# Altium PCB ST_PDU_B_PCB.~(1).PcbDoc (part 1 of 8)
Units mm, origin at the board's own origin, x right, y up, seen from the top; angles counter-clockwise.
Board outline 200 x 200 mm, 6 copper layers (Top Layer, Layer 1, Layer 2, Layer 3, Layer 4, Bottom Layer), stack 3.194 mm thick; 894 components, 723 nets, 3233 pads, 4067 vias.
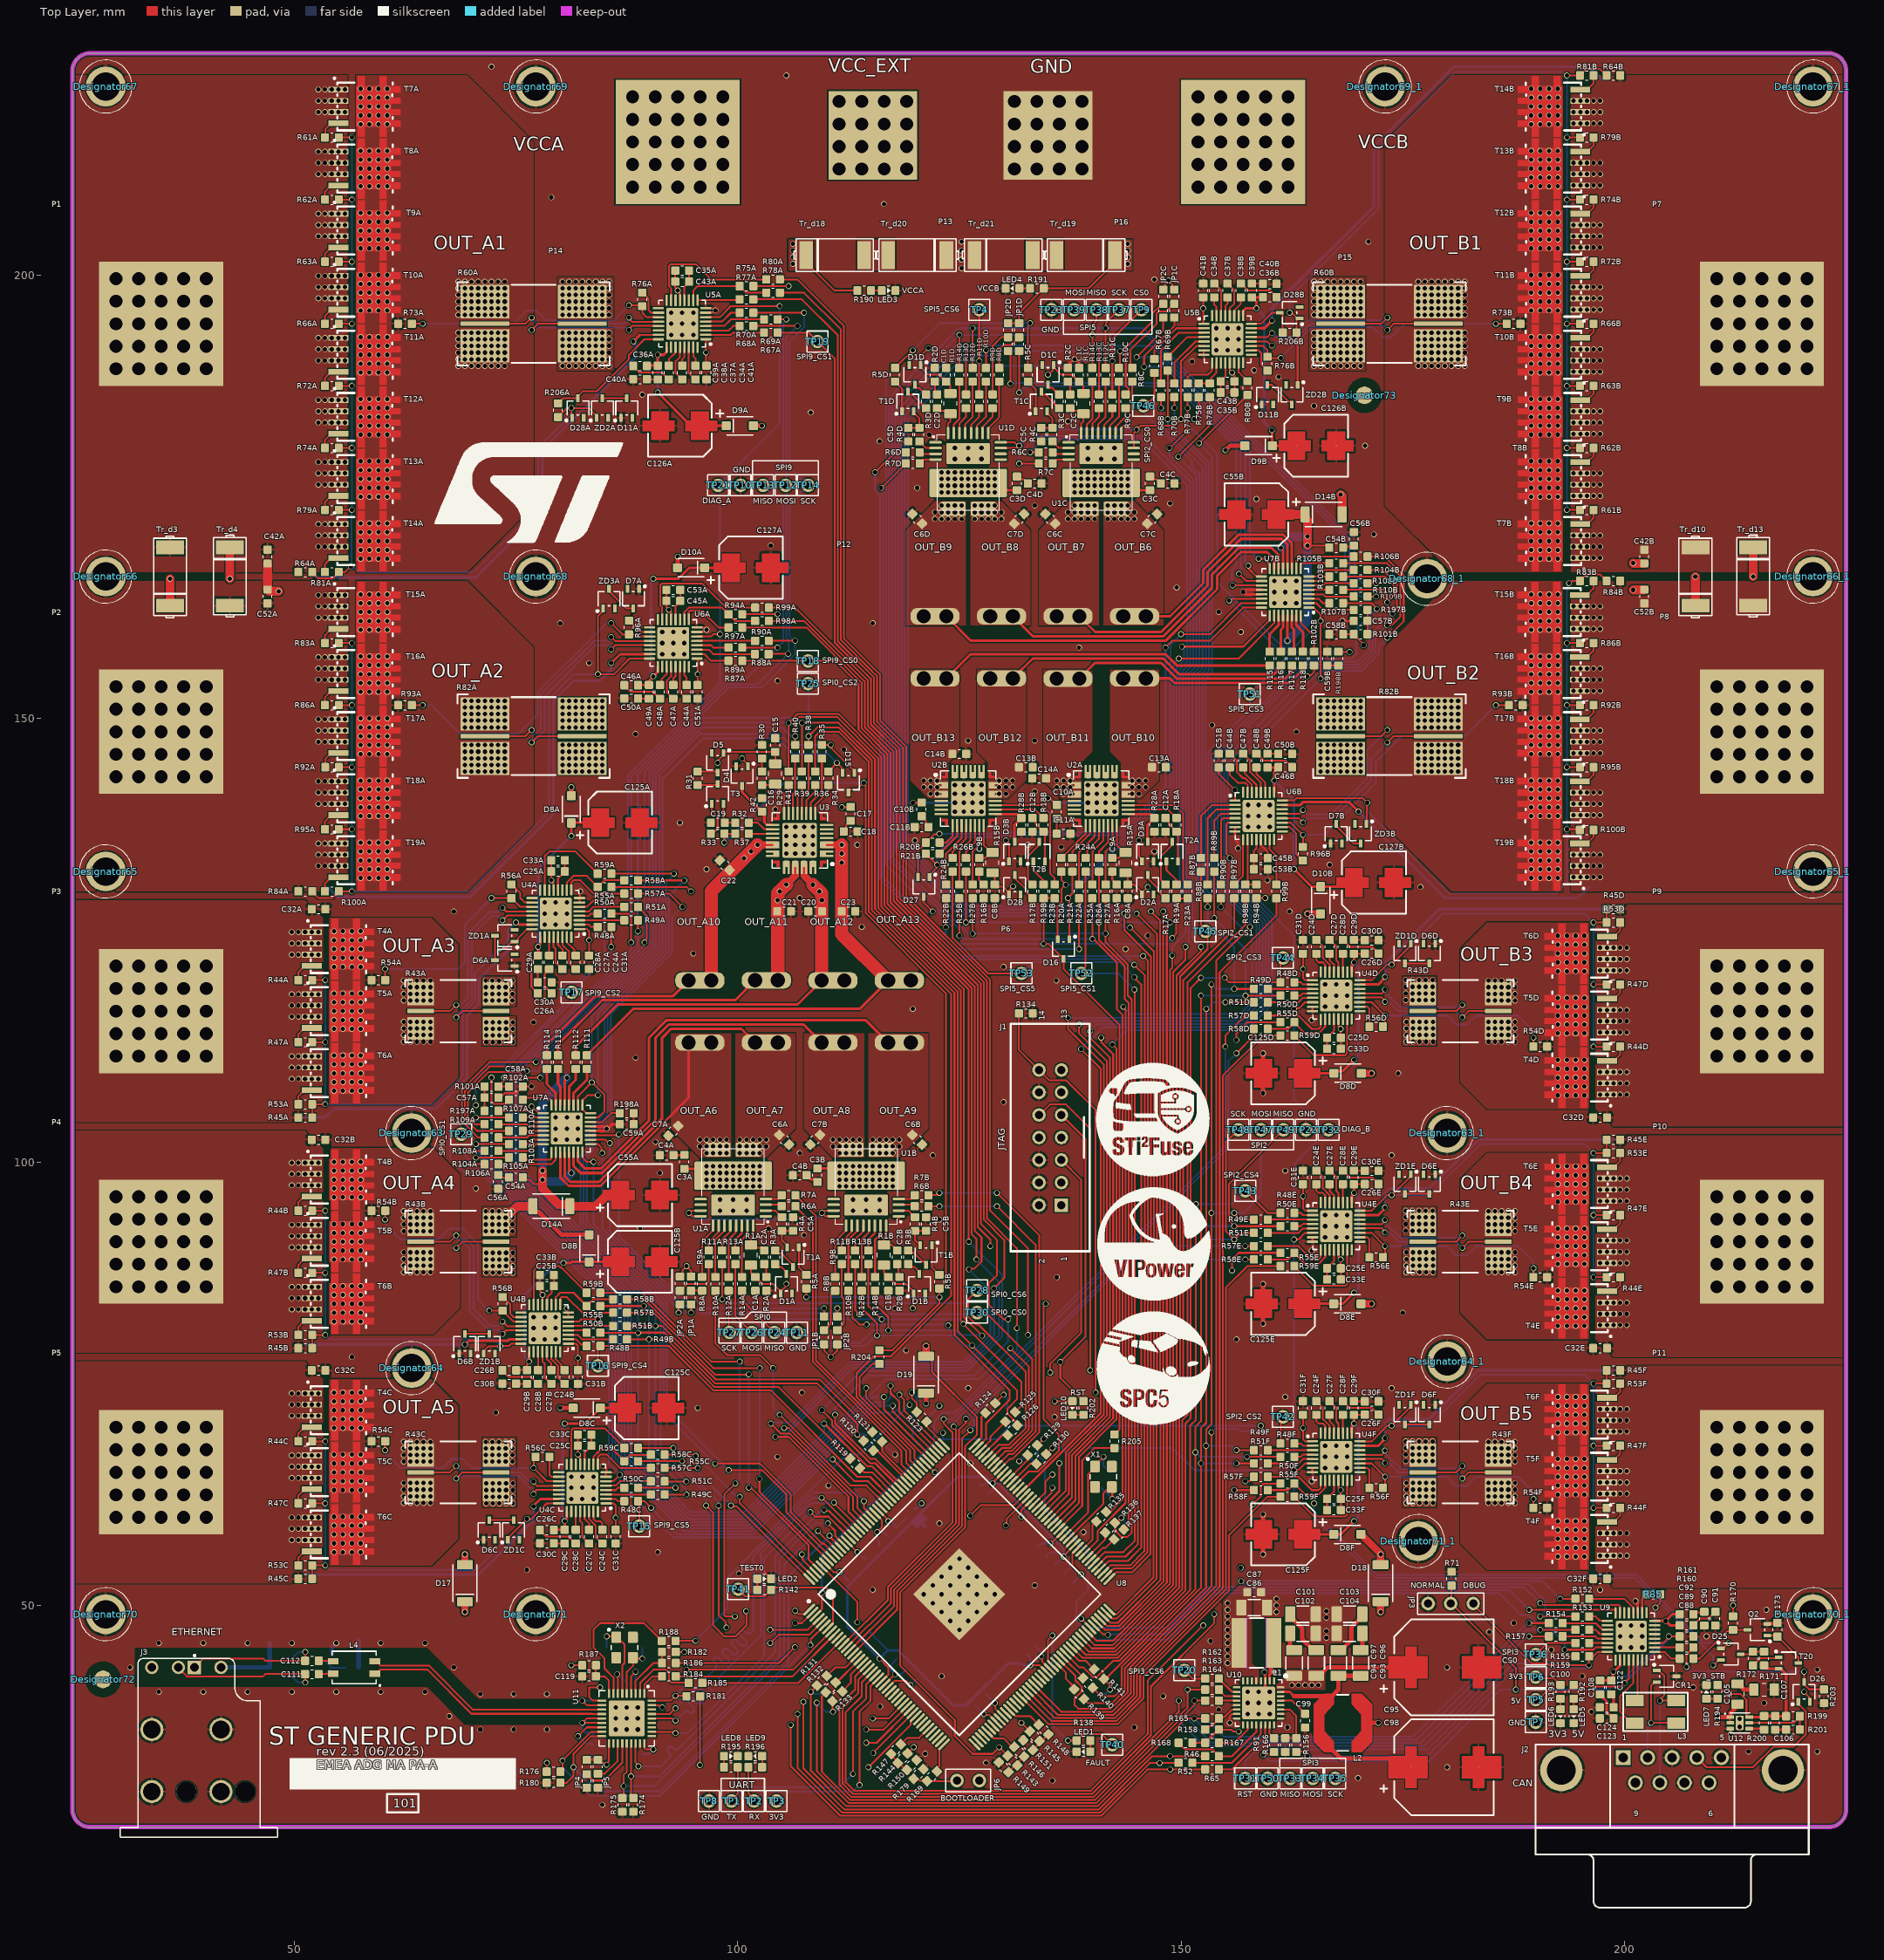
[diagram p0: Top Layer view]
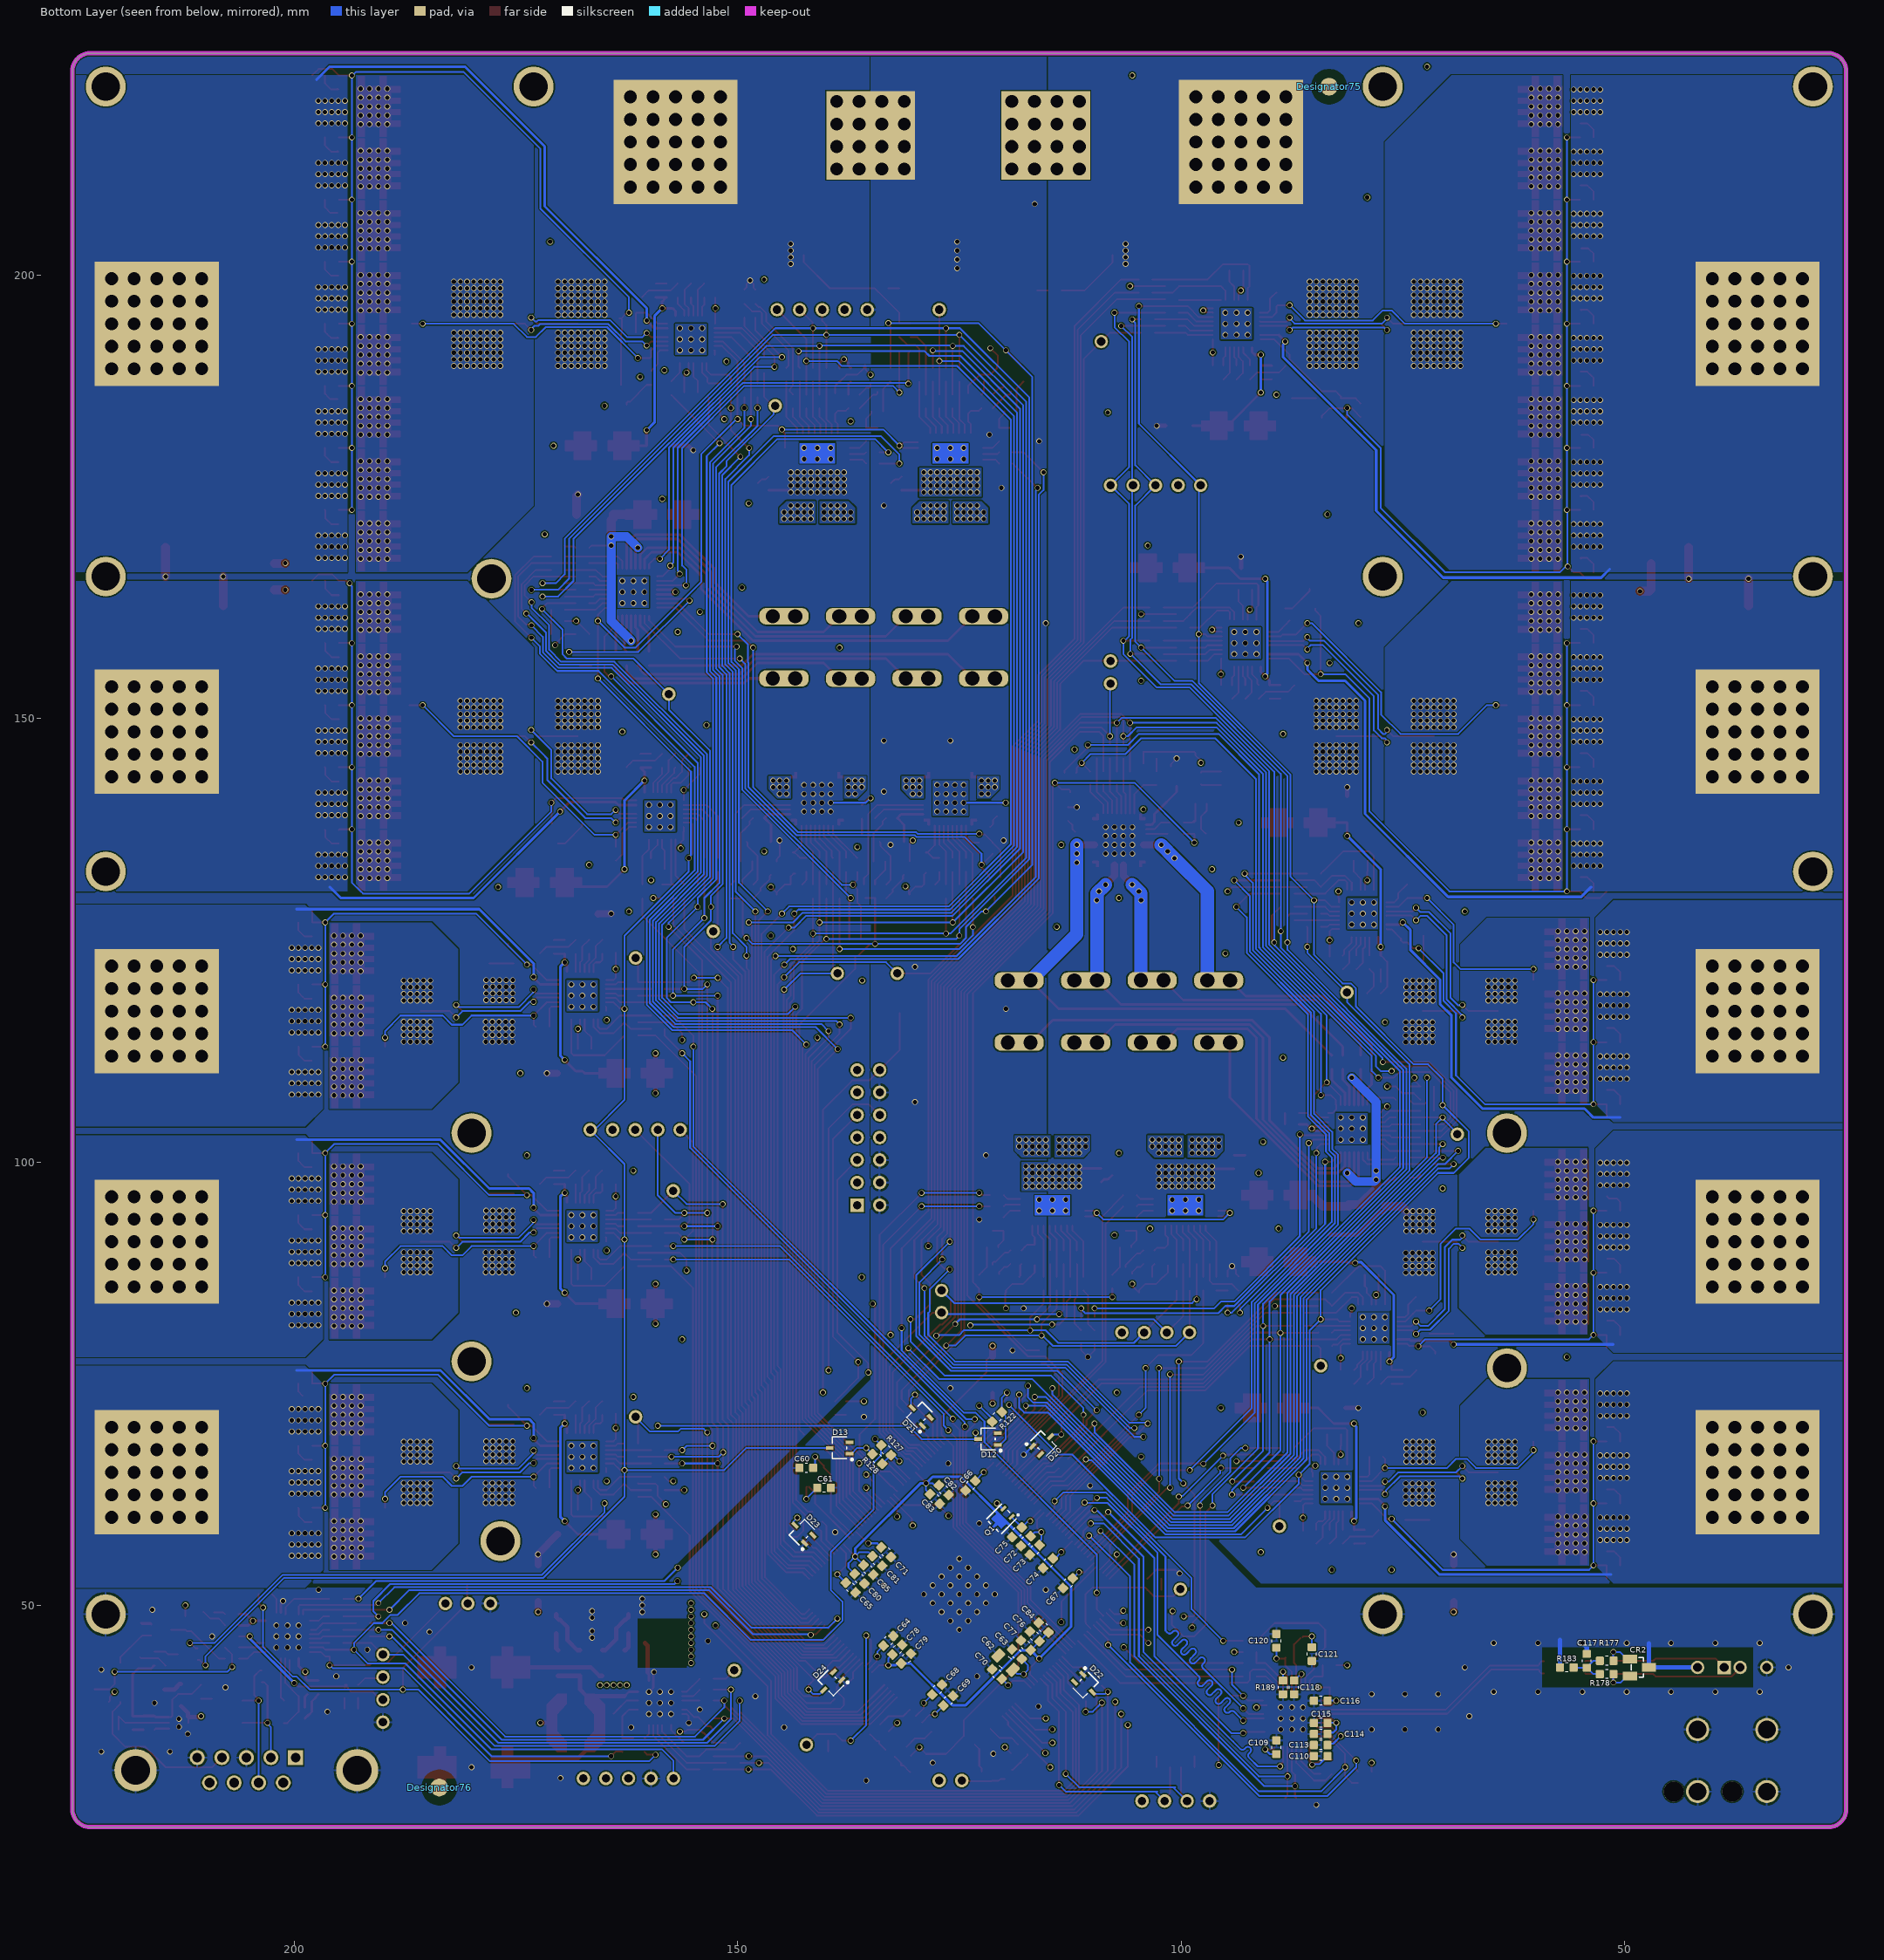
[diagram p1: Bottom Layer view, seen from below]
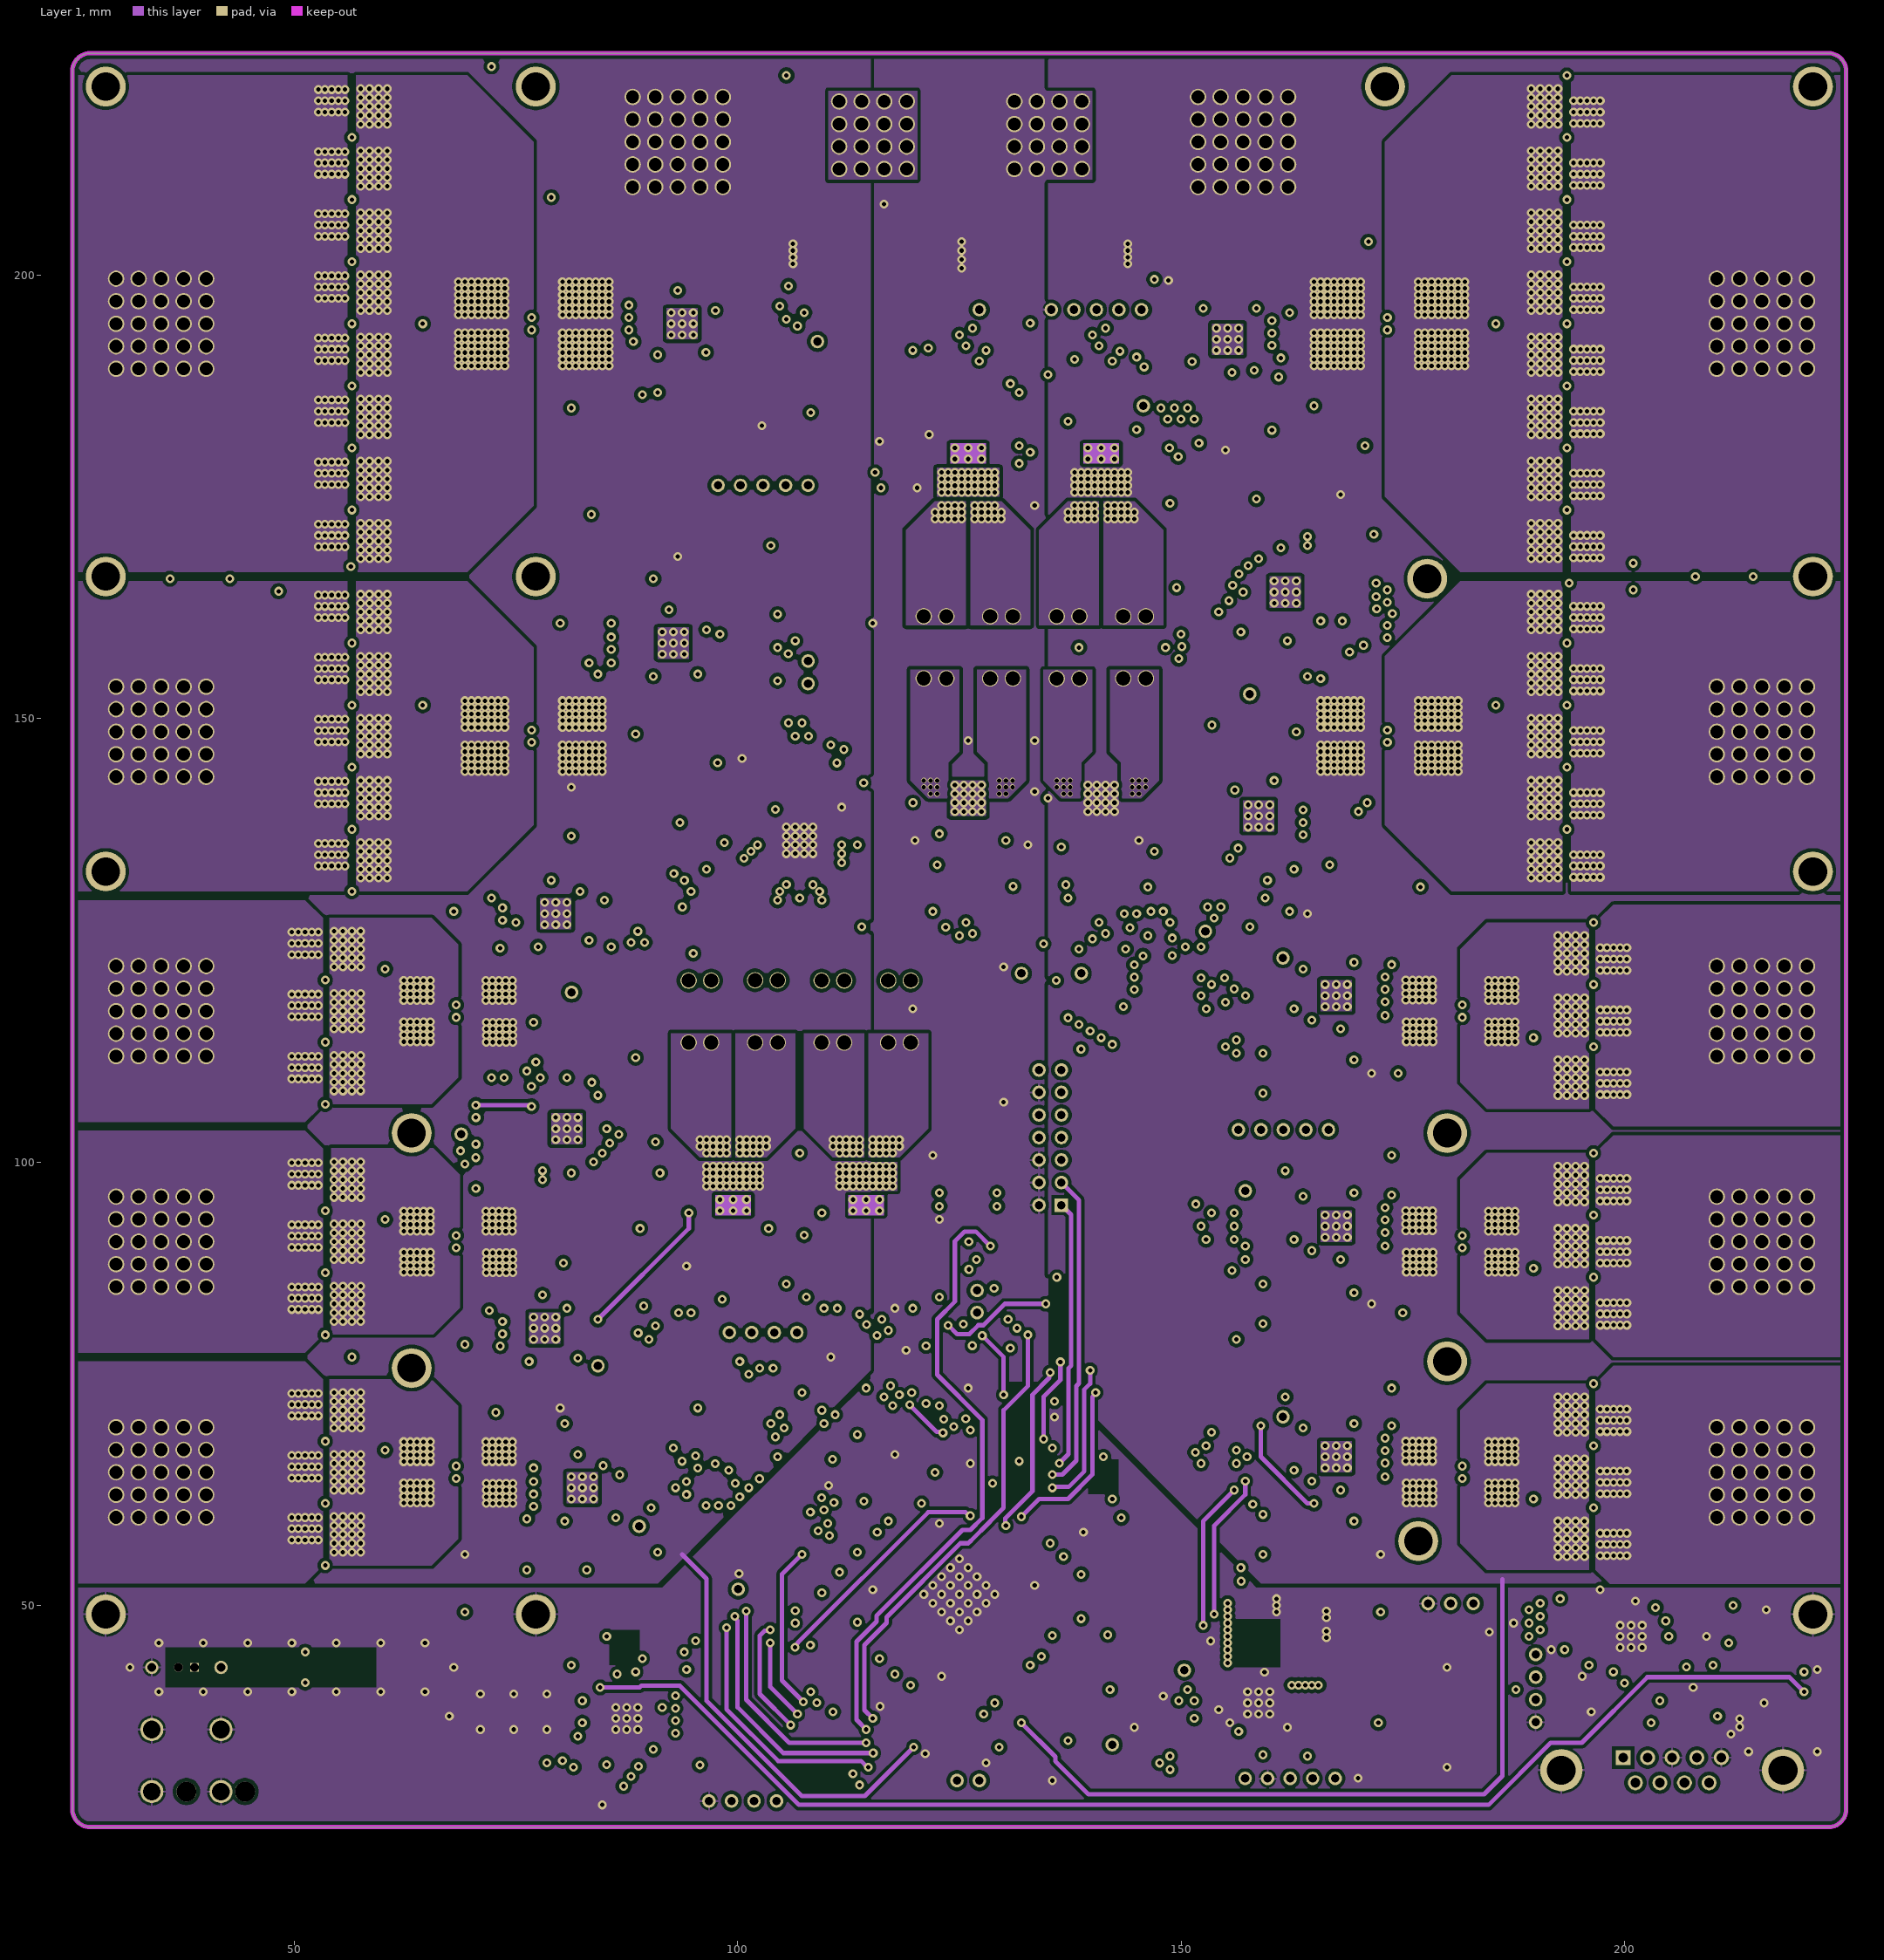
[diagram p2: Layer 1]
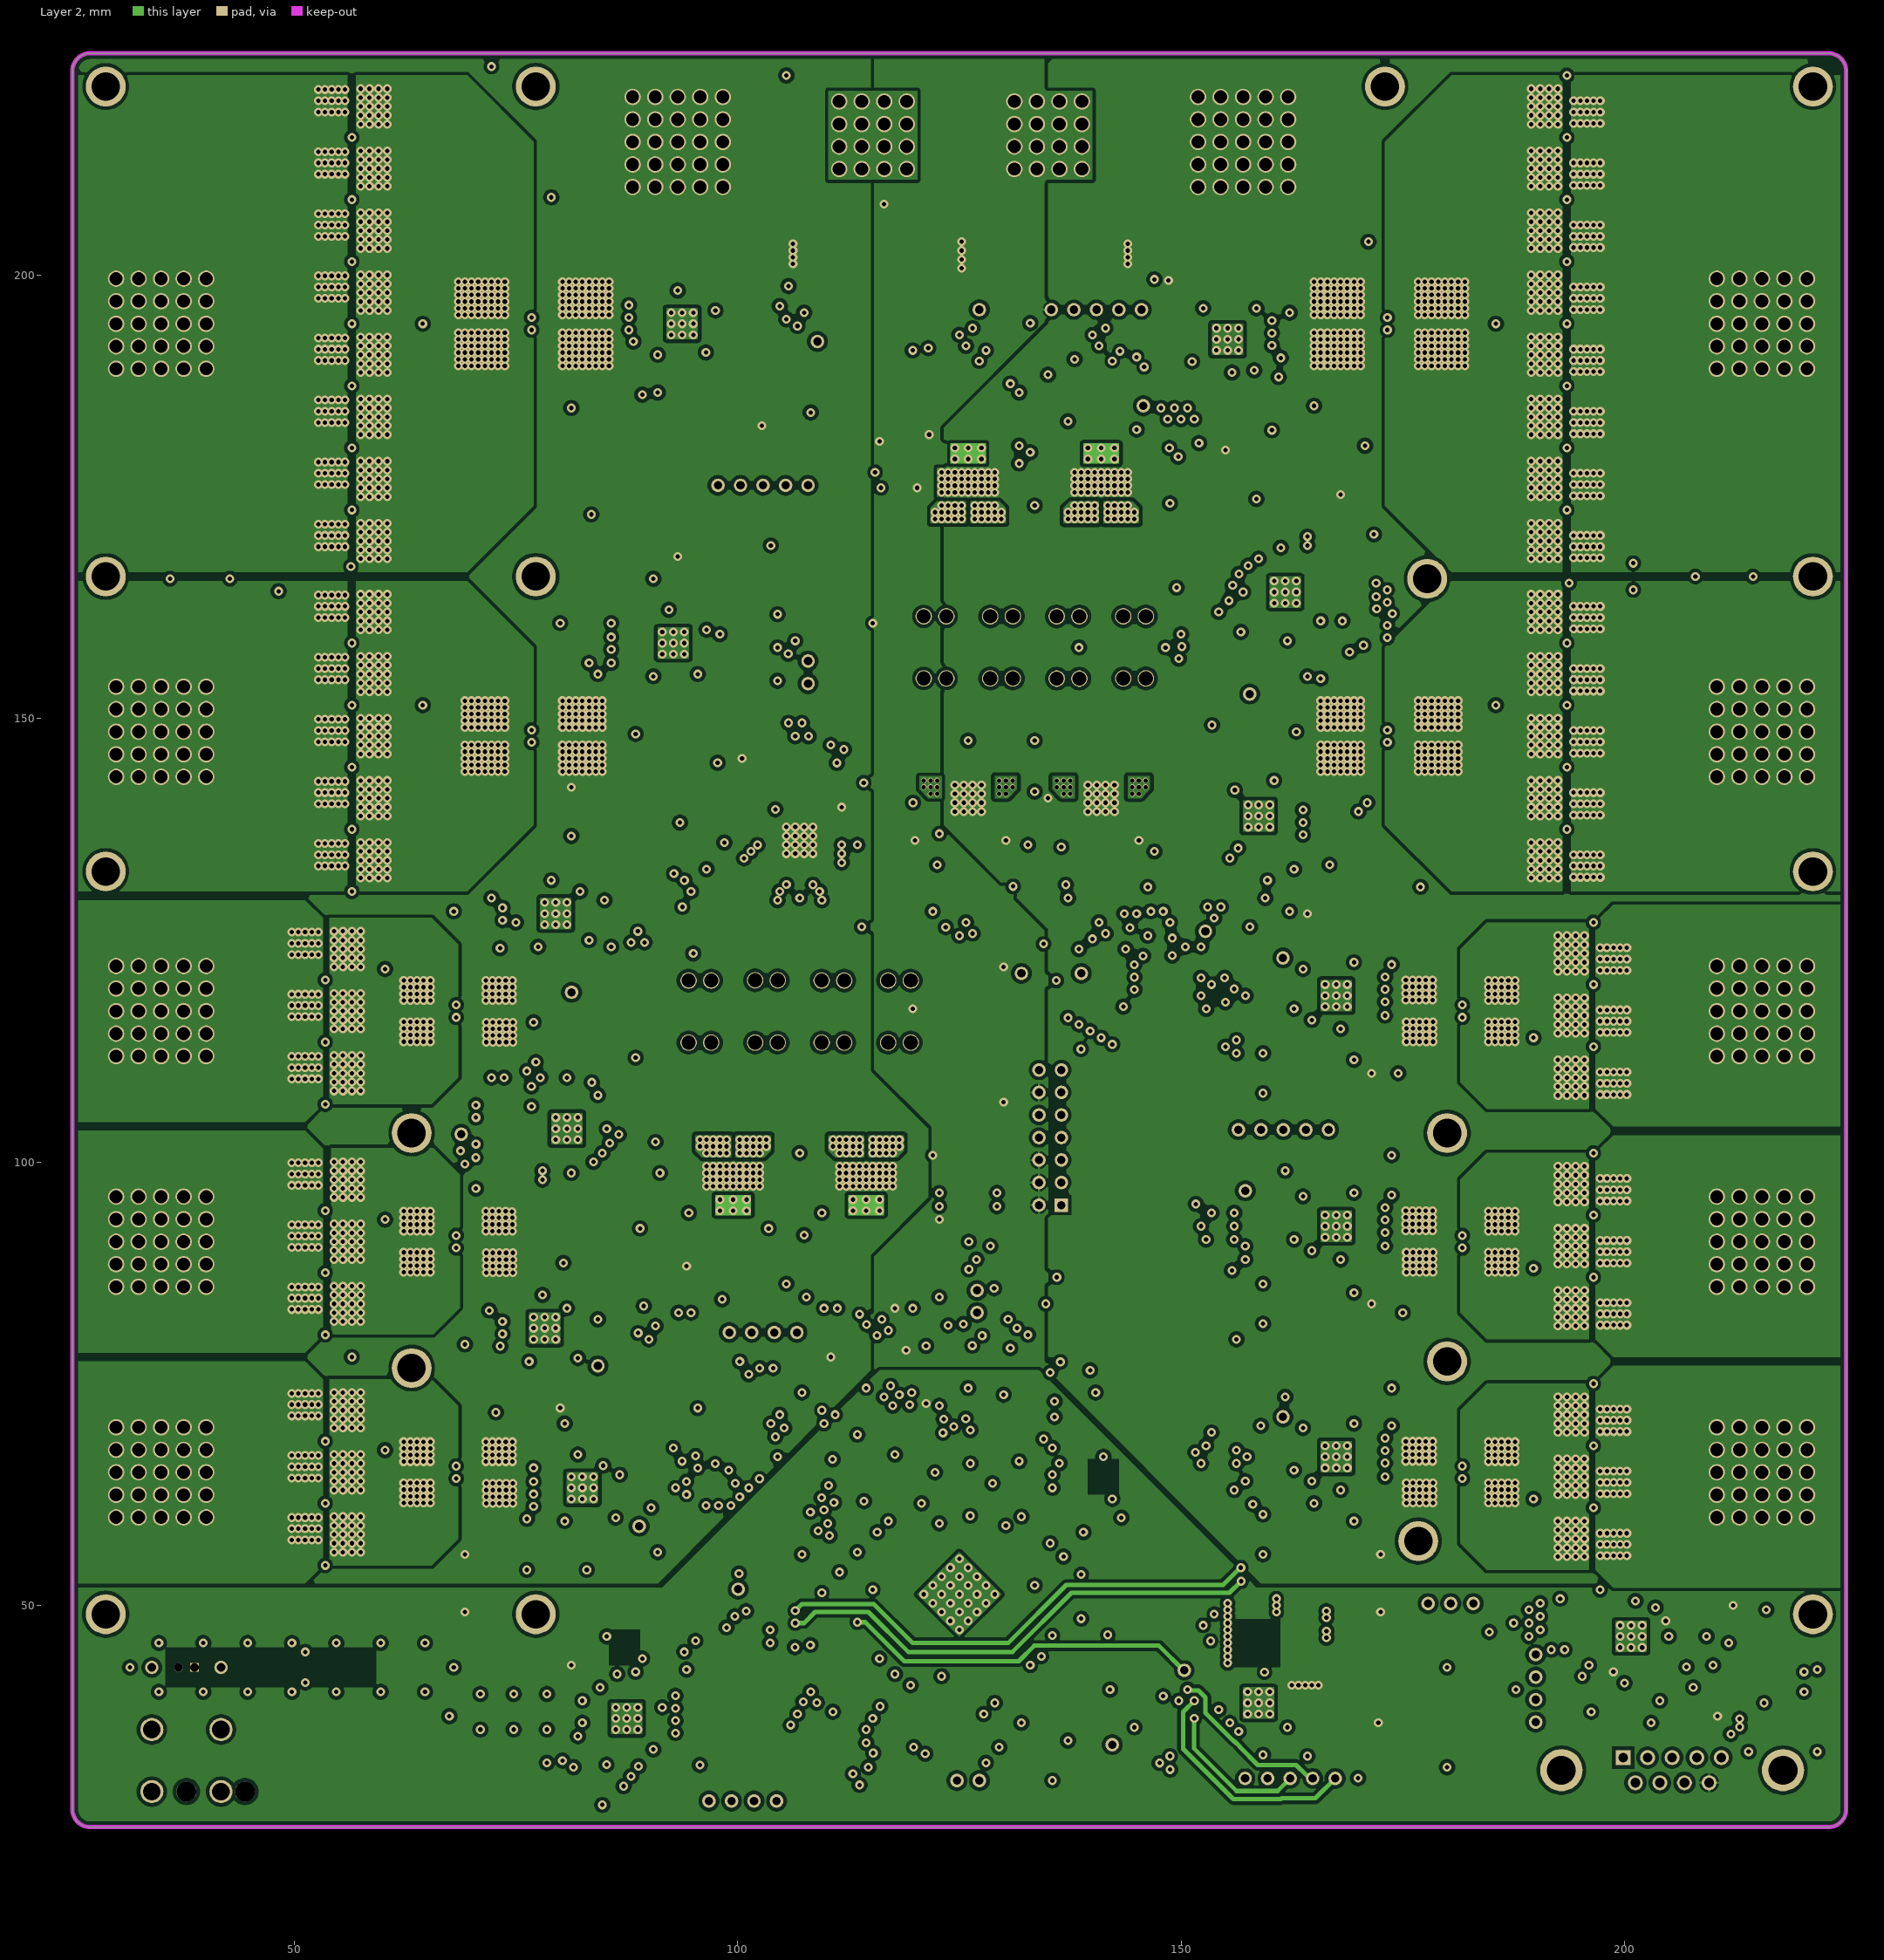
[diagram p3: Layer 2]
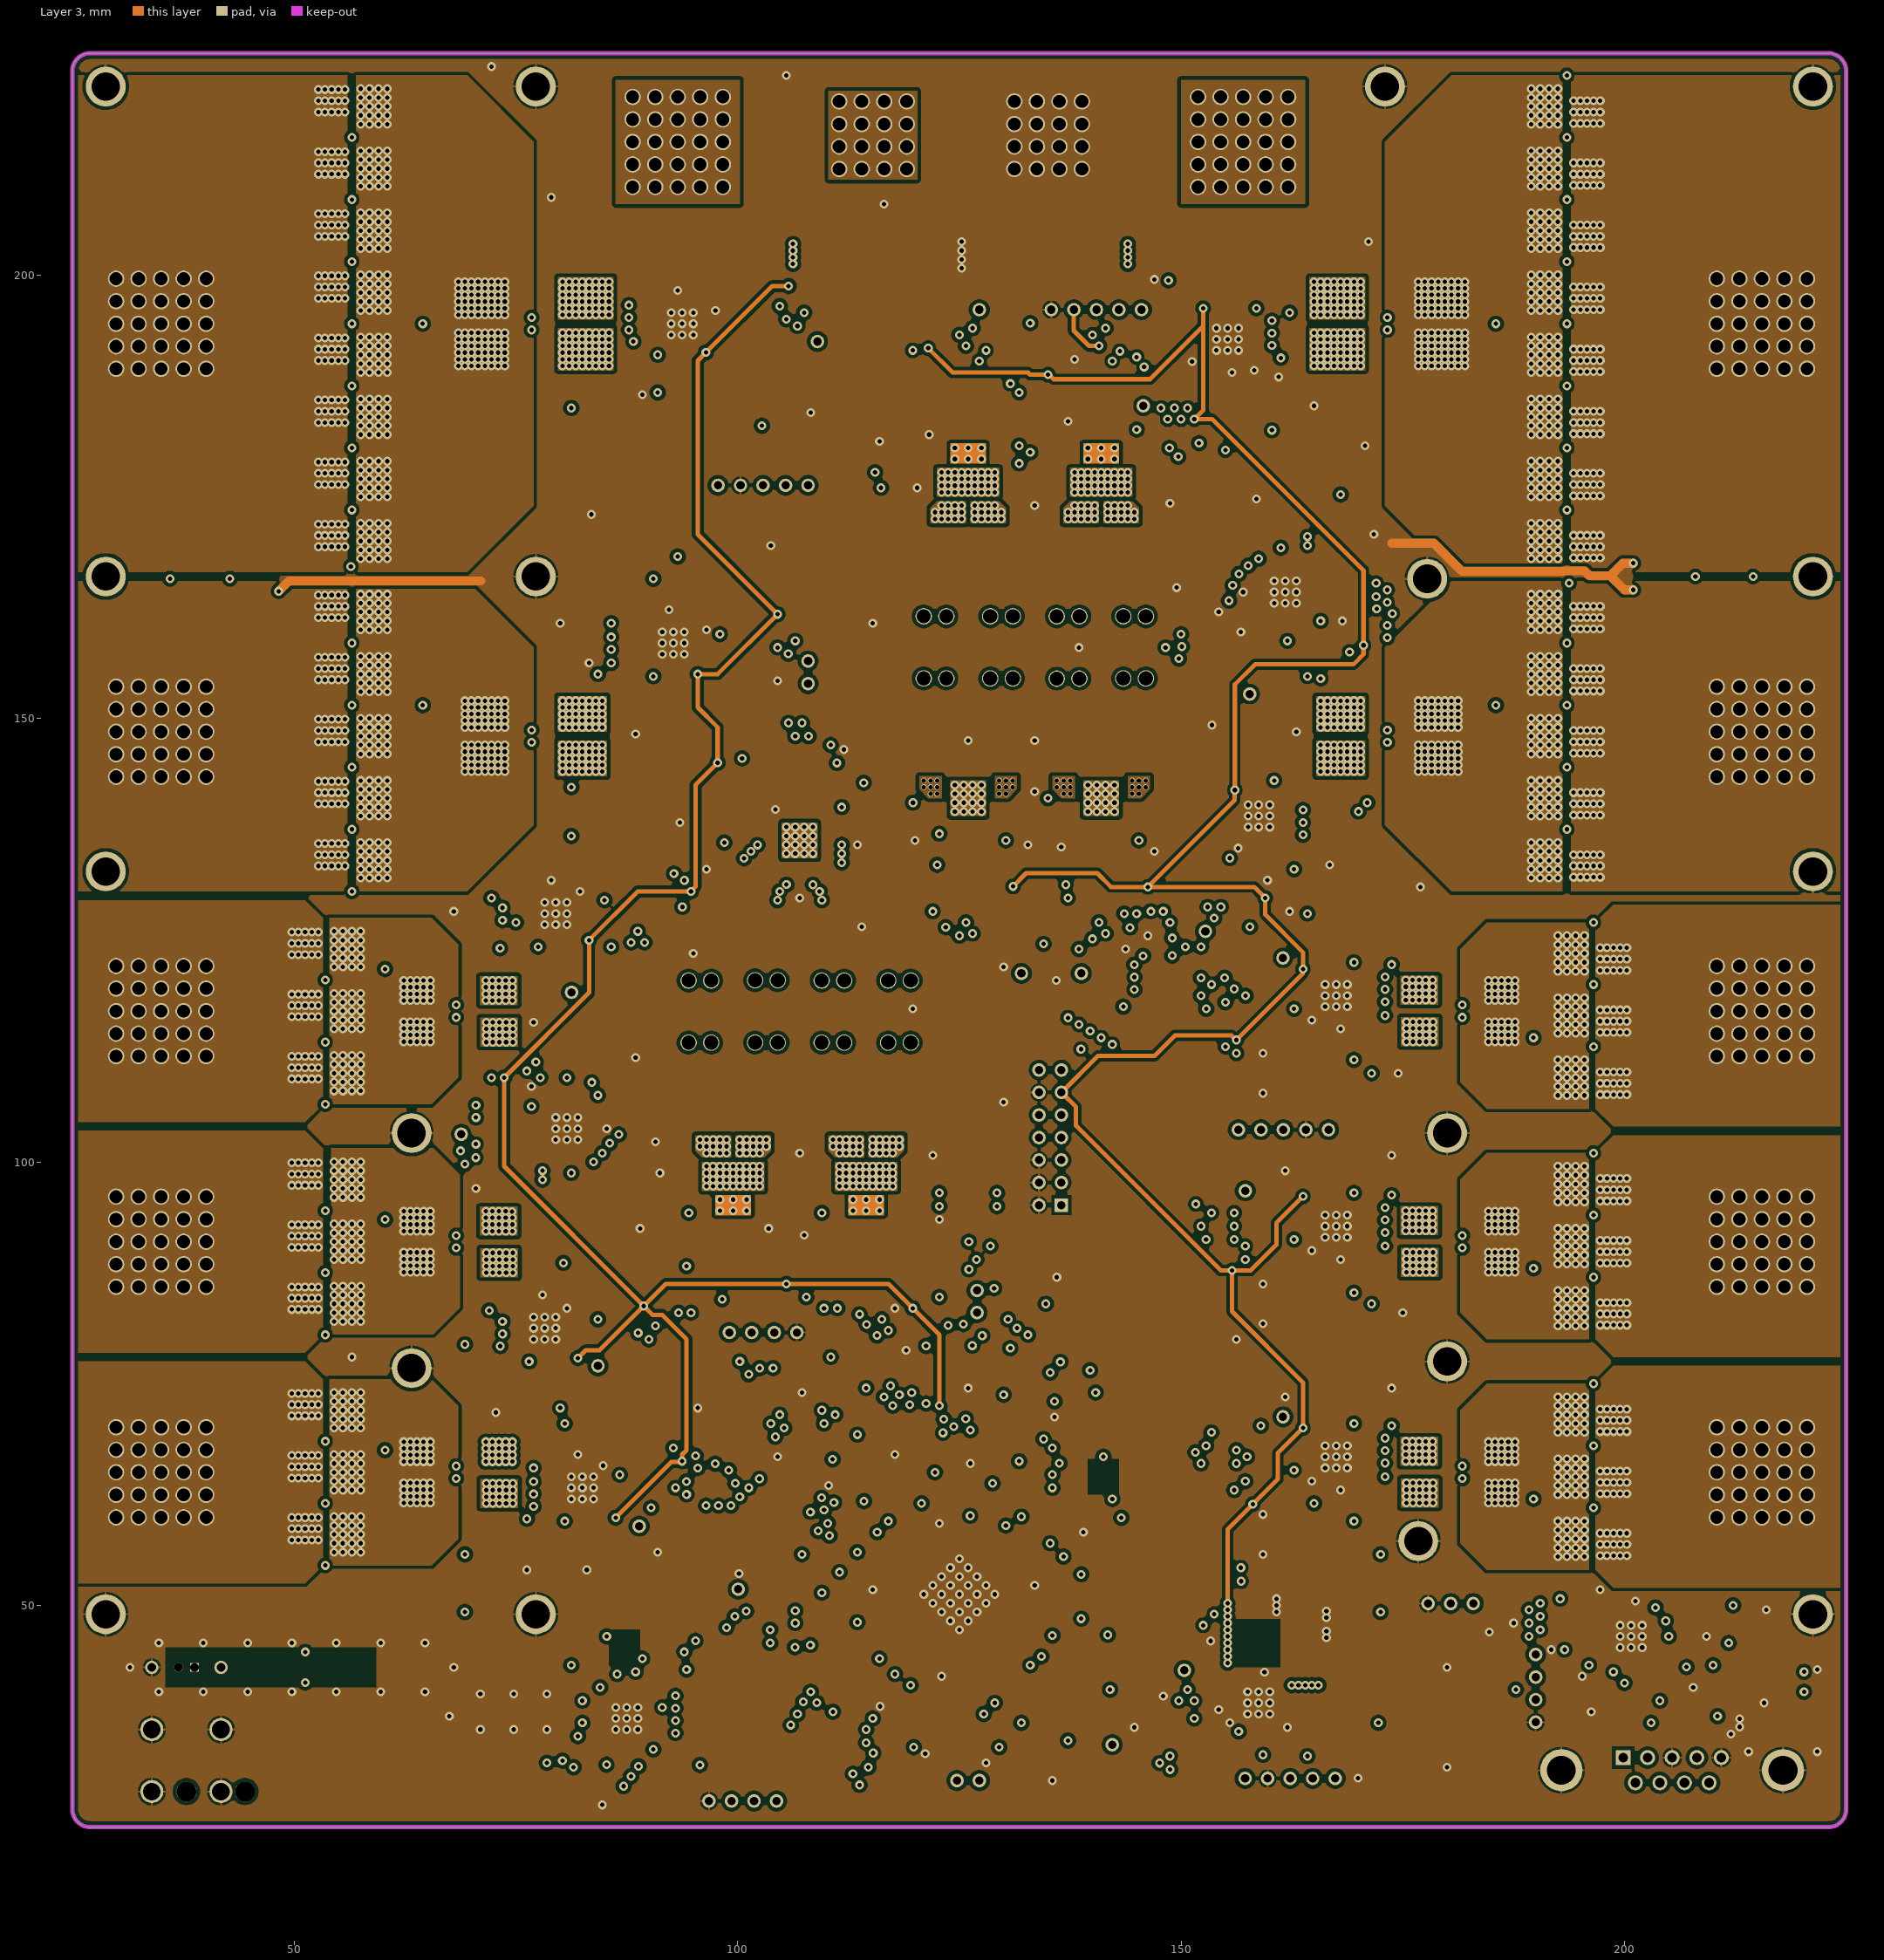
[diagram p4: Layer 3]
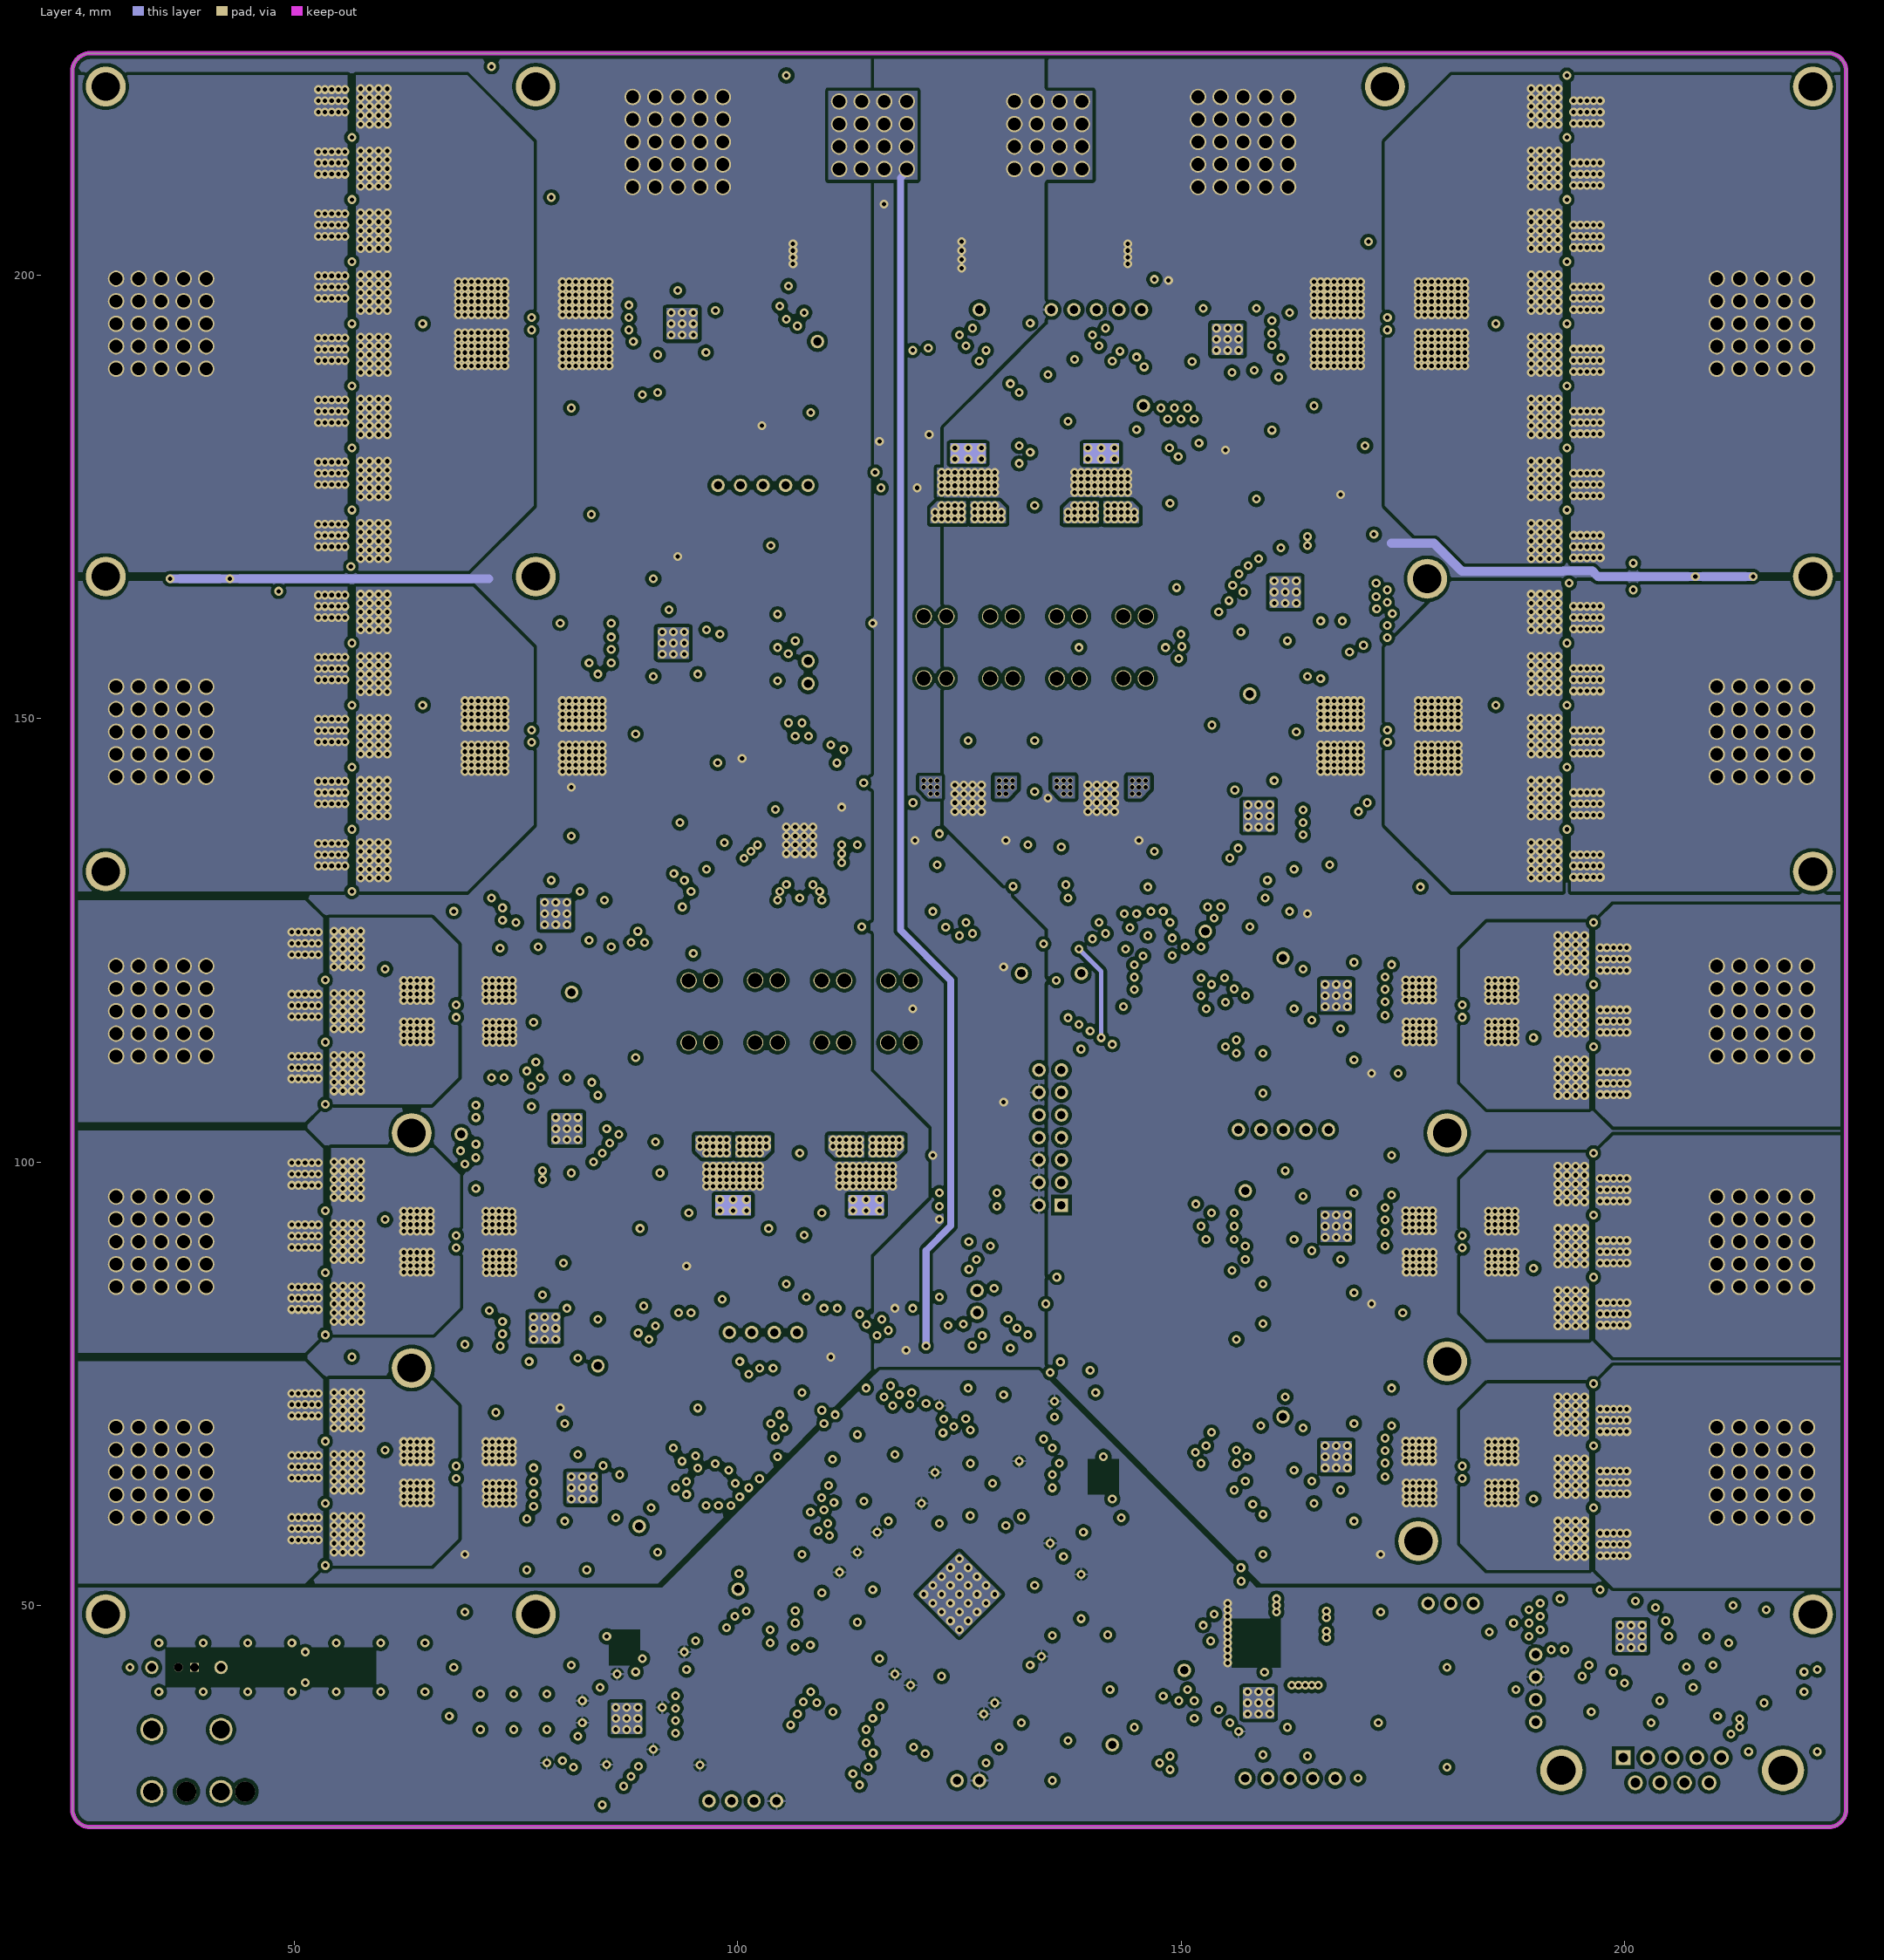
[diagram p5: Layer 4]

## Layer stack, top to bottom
Top Solder: solder mask 0.0102, Solder Resist, Dk 3.5
Top Layer: signal copper 0.035
Dielectric 2: prepreg 0.0711, PP-006, Dk 4.1
Layer 1: signal copper 0.21
Dielectric 3: prepreg 0.0711, PP-006, Dk 4.1
Layer 2: signal copper 0.21
Dielectric 1: dielectric 2, FR-4, Dk 4.8
Layer 3: signal copper 0.21
Dielectric 4: prepreg 0.0711, PP-006, Dk 4.1
Layer 4: signal copper 0.21
Dielectric 5: prepreg 0.0711, PP-006, Dk 4.1
Bottom Layer: signal copper 0.035
Bottom Solder: solder mask 0.0102, Solder Resist, Dk 3.5

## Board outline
25,27 25,223 cw(c27,223) 27,225 223,225 cw(c223,223) 225,223 225,27 cw(c223,27) 223,25 27,25 cw(c27,27)

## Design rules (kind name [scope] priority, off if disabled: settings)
Clearance Clearance_Outer [OnTopLayer or OnBottomLayer] p1: gap=0.15 ignorepadtopadclearanceinfootprint=FALSE
Clearance Clearance_Inner [not (OnTopLayer or OnBottomLayer)] p2: gap=0.4 ignorepadtopadclearanceinfootprint=FALSE
DiffPairsRouting [All] p1: maxlimit=0.254 minlimit=0.254 mostfreqgap=0.254 toplayer_minwidth=0.2 toplayer_maxwidth=0.3 toplayer_prefwidth=0.2 midlayer1_minwidth=0.2 midlayer1_maxwidth=0.3 midlayer1_prefwidth=0.2 midlayer2_minwidth=0.2 midlayer2_maxwidth=0.3 midlayer2_prefwidth=0.2 midlayer3_minwidth=0.2 midlayer3_maxwidth=0.3 midlayer3_prefwidth=0.2 midlayer4_minwidth=0.2 midlayer4_maxwidth=0.3 midlayer4_prefwidth=0.2 bottomlayer_minwidth=0.2 bottomlayer_maxwidth=0.3 bottomlayer_prefwidth=0.2 maxuncoupledlength=12.7
HoleSize [All] p1: absolutevalues=TRUE maxlimit=5 minlimit=0.025 maxpercent=80.000 minpercent=20.000
MatchedLengths "Schematic Matched Net Lengths" [InNetClass('EHT__LENGTH_MATCH')] p1: tolerance=3 checknetsindiffpair=TRUE checkdiffpairvsdiffpair=FALSE checkxsignals=FALSE checkothers=FALSE
PolygonConnect [All] p1: connectstyle=Relief reliefconductorwidth=0.254 reliefentries=4 polygonreliefangle="90 Angle" airgapwidth=0.254
RoomDefinition U_VNF9Q20SF_A1 [InComponentClass('U_VNF9Q20SF_A1')] p1: confinementstyle=ConfineIn formatcopy=TRUE lockcomponents=FALSE outline 94.676,141.721 94.676,144.779 95.629,144.779 95.629,147.56 101.926,147.56 101.926,147.779 103.426,147.779 103.426,148.529 105.074,148.529 105.074,147.779 110.324,147.779 110.324,144.779 111.074,144.779 111.074,140.779 113.574,140.779 113.574,138.074 114.279,138.074 114.279,136.426 114.029,136.426 114.029,127.426 106.779,127.426 103.721,127.426 103.721,131.788 96.884,131.788 96.884,136.176 96.221,136.176 96.221,138.94 95.629,138.94 95.629,141.721
RoomDefinition U_VNF9D5SF_B2 [InComponentClass('U_VNF9D5SF_B2')] p2: confinementstyle=ConfineIn formatcopy=TRUE lockcomponents=FALSE outline 119,128.5 136.75,128.5 136.75,147 119,147
RoomDefinition U_VNF9D5SF_B1 [InComponentClass('U_VNF9D5SF_B1')] p3: confinementstyle=ConfineIn formatcopy=TRUE lockcomponents=FALSE outline 132.25,128.5 151.75,128.5 151.75,145.5 132.25,145.5
RoomDefinition U_VNF1248+3F8_B1 [InComponentClass('U_VNF1248+3F8_B1')] p4: confinementstyle=ConfineIn formatcopy=TRUE lockcomponents=FALSE outline 200.279,129.824 200.279,112.676 199.451,112.676 199.451,106.296 198.779,106.296 198.779,104.676 195.721,104.676 195.721,106.296 190.669,106.296 190.669,111.926 165.721,111.926 165.721,113.426 160.471,113.426 160.471,114.176 157.471,114.176 157.471,120.324 160.471,120.324 160.471,121.074 162.926,121.074 162.926,125.779 169.971,125.779 169.971,125.824 173.129,125.824 173.129,126.06 190.669,126.06 190.669,127.589 197.221,127.589 197.221,129.824
RoomDefinition U_L99SP08_B1 [InComponentClass('U_L99SP08_B1')] p5: confinementstyle=ConfineIn formatcopy=TRUE lockcomponents=FALSE outline 151.296,170.896 151.296,178.604 161.004,178.604 161.004,178.38 166.33,178.38 166.33,171.779 170.324,171.779 170.324,169.074 171.779,169.074 171.779,158.676 167.324,158.676 167.324,155.221 164.426,155.221 164.426,160.644 158.144,160.644 158.144,170.896
RoomDefinition U_VNF1248+3F8_A1 [InComponentClass('U_VNF1248+3F8_A1')] p6: confinementstyle=ConfineIn formatcopy=TRUE lockcomponents=FALSE outline 49.721,104.176 49.721,121.324 50.549,121.324 50.549,127.704 51.221,127.704 51.221,129.324 73.676,129.324 73.676,132.029 78.221,132.029 78.221,134.824 81.279,134.824 81.279,133.324 86.529,133.324 86.529,132.574 89.529,132.574 89.529,126.426 86.529,126.426 86.529,125.676 84.074,125.676 84.074,120.971 79.779,120.971 79.779,118.176 74.854,118.176 74.854,113.146 59.331,113.146 59.331,106.411 52.779,106.411 52.779,104.176
RoomDefinition U_VNF1248+5F8_A1 [InComponentClass('U_VNF1248+5F8_A1')] p7: confinementstyle=ConfineIn formatcopy=TRUE lockcomponents=FALSE outline 39.676,129.221 39.676,132.279 52.721,132.279 52.721,159.324 53.549,159.324 53.549,165.704 83.379,165.704 83.379,166.06 90.371,166.06 90.371,165.324 94.279,165.324 94.279,163.324 104.279,163.324 104.279,157.926 104.254,157.926 104.254,156.426 101.279,156.426 101.279,155.676 96.58,155.676 96.58,154.894 96.324,154.894 96.324,151.471 89.529,151.471 89.529,151.426 85.954,151.426 85.954,142.946 62.331,142.946 62.331,130.411 55.779,130.411 55.779,129.676 41.324,129.676 41.324,129.221
RoomDefinition U_VNF1248+5F8_B1 [InComponentClass('U_VNF1248+5F8_B1')] p8: confinementstyle=ConfineIn formatcopy=TRUE lockcomponents=FALSE outline 151.426,131.971 151.426,135.029 153.426,135.029 153.426,146.779 160.221,146.779 160.221,146.824 164.546,146.824 164.546,153.054 187.619,153.054 187.619,165.589 194.221,165.589 194.221,166.324 207.676,166.324 207.676,166.779 209.324,166.779 209.324,163.721 197.279,163.721 197.279,143.676 197.265,143.676 197.265,136.599 196.401,136.599 196.401,130.296 161.574,130.296 161.574,128.971 152.176,128.971 152.176,131.971
RoomDefinition U_VNF9D1M5Q_B2 [InComponentClass('U_VNF9D1M5Q_B2')] p9: confinementstyle=ConfineIn formatcopy=TRUE lockcomponents=FALSE outline 133.5,195.25 117,195.25 117,171 133.5,171
RoomDefinition U_VNF9D1M5Q_B1 [InComponentClass('U_VNF9D1M5Q_B1')] p10: confinementstyle=ConfineIn formatcopy=TRUE lockcomponents=FALSE outline 148.5,195.25 132,195.25 132,171 148.5,171
RoomDefinition U_L99SP08_A1 [InComponentClass('U_L99SP08_A1')] p11: confinementstyle=ConfineIn formatcopy=TRUE lockcomponents=FALSE outline 91.204,97.104 91.204,89.396 81.496,89.396 81.496,89.62 76.17,89.62 76.17,96.221 72.176,96.221 72.176,98.926 70.721,98.926 70.721,109.324 75.176,109.324 75.176,112.779 78.074,112.779 78.074,107.356 84.356,107.356 84.356,97.104
RoomDefinition U_VNF1248+3F8_B3 [InComponentClass('U_VNF1248+3F8_B3')] p12: confinementstyle=ConfineIn formatcopy=TRUE lockcomponents=FALSE outline 200.279,77.824 200.279,60.676 199.451,60.676 199.451,54.296 198.779,54.296 198.779,52.676 195.721,52.676 195.721,54.296 190.669,54.296 190.669,59.926 165.721,59.926 165.721,61.426 160.471,61.426 160.471,62.176 157.471,62.176 157.471,68.324 160.471,68.324 160.471,69.074 162.926,69.074 162.926,73.779 169.971,73.779 169.971,73.824 173.129,73.824 173.129,74.06 190.669,74.06 190.669,75.589 197.221,75.589 197.221,77.824
RoomDefinition U_VNF1248+8F8_B1 [InComponentClass('U_VNF1248+8F8_B1')] p13: confinementstyle=ConfineIn formatcopy=TRUE lockcomponents=FALSE outline 146.176,188.471 146.176,191.529 151.42,191.529 151.42,196.356 151.676,196.356 151.676,199.779 158.471,199.779 158.471,199.824 187.669,199.824 187.669,201.589 187.669,222.589 194.221,222.589 194.221,223.324 207.676,223.324 207.676,224.279 209.324,224.279 209.324,221.221 197.279,221.221 197.279,172.676 196.451,172.676 196.451,166.296 187.669,166.296 187.669,183.94 157.879,183.94 157.879,185.471 146.926,185.471 146.926,188.471
RoomDefinition U_VNF1248+8F8_A1 [InComponentClass('U_VNF1248+8F8_A1')] p14: confinementstyle=ConfineIn formatcopy=TRUE lockcomponents=FALSE outline 39.676,165.221 39.676,168.279 52.721,168.279 52.721,216.324 53.549,216.324 53.549,222.704 62.331,222.704 62.331,201.324 95.279,201.324 95.279,200.324 105.529,200.324 105.529,197.176 105.279,197.176 105.279,192.676 97.58,192.676 97.58,190.894 97.324,190.894 97.324,187.471 90.529,187.471 90.529,187.426 88.371,187.426 88.371,182.44 62.331,182.44 62.331,166.411 55.779,166.411 55.779,165.676 41.324,165.676 41.324,165.221
RoomDefinition U_VNF1248+3F8_B2 [InComponentClass('U_VNF1248+3F8_B2')] p15: confinementstyle=ConfineIn formatcopy=TRUE lockcomponents=FALSE outline 200.279,103.824 200.279,86.676 199.451,86.676 199.451,80.296 198.779,80.296 198.779,78.676 195.721,78.676 195.721,80.296 190.669,80.296 190.669,85.926 165.721,85.926 165.721,87.426 160.471,87.426 160.471,88.176 157.471,88.176 157.471,94.324 160.471,94.324 160.471,95.074 162.926,95.074 162.926,99.779 169.971,99.779 169.971,99.824 173.129,99.824 173.129,100.06 190.669,100.06 190.669,101.589 197.221,101.589 197.221,103.824
RoomDefinition U_VNF1248+3F8_A3 [InComponentClass('U_VNF1248+3F8_A3')] p16: confinementstyle=ConfineIn formatcopy=TRUE lockcomponents=FALSE outline 49.721,52.176 49.721,69.324 50.549,69.324 50.549,75.704 51.221,75.704 51.221,77.324 54.279,77.324 54.279,75.704 59.331,75.704 59.331,70.074 84.279,70.074 84.279,68.574 89.529,68.574 89.529,67.824 92.529,67.824 92.529,61.676 89.529,61.676 89.529,60.926 87.074,60.926 87.074,56.221 80.029,56.221 80.029,56.176 76.871,56.176 76.871,55.94 59.331,55.94 59.331,54.411 52.779,54.411 52.779,52.176
RoomDefinition U_VNF1248+3F8_A2 [InComponentClass('U_VNF1248+3F8_A2')] p17: confinementstyle=ConfineIn formatcopy=TRUE lockcomponents=FALSE outline 49.721,78.176 49.721,95.324 50.549,95.324 50.549,101.704 51.221,101.704 51.221,103.324 54.279,103.324 54.279,101.704 59.331,101.704 59.331,96.074 84.279,96.074 84.279,94.574 89.529,94.574 89.529,93.824 92.529,93.824 92.529,87.676 89.529,87.676 89.529,86.926 87.074,86.926 87.074,82.221 80.029,82.221 80.029,82.176 76.871,82.176 76.871,81.94 59.331,81.94 59.331,80.411 52.779,80.411 52.779,78.176
RoomDefinition U_VNF9D1M5Q_A2 [InComponentClass('U_VNF9D1M5Q_A2')] p18: confinementstyle=ConfineIn formatcopy=TRUE lockcomponents=FALSE outline 107,79.75 123.5,79.75 123.5,104 107,104
RoomDefinition U_VNF9D1M5Q_A1 [InComponentClass('U_VNF9D1M5Q_A1')] p19: confinementstyle=ConfineIn formatcopy=TRUE lockcomponents=FALSE outline 92,79.75 108.5,79.75 108.5,104 92,104
RoutingVias [All] p1: holewidth=0.711 width=1.27 viastyle="Through Hole" minholewidth=0.711 minwidth=1.27 maxholewidth=0.711 maxwidth=1.27 useviatemplates=TRUE viatemplateguid#1={04CFE264-F8F2-4C08-A233-AB3A3D66539B} viatemplatename#1=v65h50z100m0_2670034071
SolderMaskExpansion [All] p1: expansion=0.05 istentingtop=FALSE
SupplyNets "Schematic Supply Nets_8" [InNet('GND')] p1: voltage=0.000
SupplyNets "Schematic Supply Nets_7" [InNet('VCCB')] p2: voltage=0.000
SupplyNets "Schematic Supply Nets_6" [InNet('VCC')] p3: voltage=0.000
SupplyNets "Schematic Supply Nets_5" [InNet('VCC_EXT')] p4: voltage=0.000
SupplyNets "Schematic Supply Nets_4" [InNet('3V3')] p5: voltage=0.000
SupplyNets "Schematic Supply Nets_3" [InNet('VREF')] p6: voltage=0.000
SupplyNets "Schematic Supply Nets_2" [InNet('5V')] p7: voltage=0.000
SupplyNets "Schematic Supply Nets_1" [InNet('3V3_STB')] p8: voltage=0.000
SupplyNets "Schematic Supply Nets" [InNet('VCCA')] p9: voltage=0.000
UnRoutedNet [All] p1: checkbadconnections=TRUE
Width Width_Outer [OnTopLayer or OnBottomLayer] p1: maxlimit=5 minlimit=0.2 preferedwidth=0.2
Width Width_Inner [not (OnTopLayer or OnBottomLayer)] p2: maxlimit=5 minlimit=0.5 preferedwidth=0.5
27 further rules are at their usual default settings.

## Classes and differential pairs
channel class VNF9D5SF: U_VNF9D5SF_B1 U_VNF9D5SF_B2
net class EHT__LENGTH_MATCH: ETH0_REF_CLK ETH0_RXD0 ETH0_RXD1 ETH0_TXD0 ETH0_TXD1
component class U_Ethernet: C109 C110 C111 C112 C113 C114 C115 C116 C117 C118 C119 C120 C121 CR2 J3 JP4 JP5 L4 R174 R175 R176 R177 R178 R180 R181 R182 R183 R184 R185 R186 R187 R188 R189 U11 X2
channel class VNF1248+8F8: U_VNF1248+8F8_A1 U_VNF1248+8F8_B1
channel class VNF1248+5F8: U_VNF1248+5F8_A1 U_VNF1248+5F8_B1
channel class VNF1248+3F8: U_VNF1248+3F8_A1 U_VNF1248+3F8_A2 U_VNF1248+3F8_A3 U_VNF1248+3F8_B1 U_VNF1248+3F8_B2 U_VNF1248+3F8_B3
channel class VNF9D1M5Q: U_VNF9D1M5Q_A1 U_VNF9D1M5Q_A2 U_VNF9D1M5Q_B1 U_VNF9D1M5Q_B2
channel class L99SP08: U_L99SP08_A1 U_L99SP08_B1
component class U_VNF1248+8F8_B1: C34B C35B C36B C37B C38B C39B C40B C41B C42B C43B C126B D9B D11B D28B R60B R61B R62B R63B R64B R66B R67B R68B R69B R70B R72B R73B R74B R75B R76B R77B R78B R79B R80B R81B R206B T7B T8B T9B T10B T11B T12B T13B T14B U5B ZD2B
component class U_VNF1248+8F8_A1: C34A C35A C36A C37A C38A C39A C40A C41A C42A C43A C126A D9A D11A D28A R60A R61A R62A R63A R64A R66A R67A R68A R69A R70A R72A R73A R74A R75A R76A R77A R78A R79A R80A R81A R206A T7A T8A T9A T10A T11A T12A T13A T14A U5A ZD2A
component class U_VNF1248+5F8_B1: C44B C45B C46B C47B C48B C49B C50B C51B C52B C53B C127B D7B D10B R82B R83B R84B R86B R87B R88B R89B R90B R92B R93B R94B R95B R96B R97B R98B R99B R100B T15B T16B T17B T18B T19B U6B ZD3B
component class U_VNF1248+5F8_A1: C44A C45A C46A C47A C48A C49A C50A C51A C52A C53A C127A D7A D10A R82A R83A R84A R86A R87A R88A R89A R90A R92A R93A R94A R95A R96A R97A R98A R99A R100A T15A T16A T17A T18A T19A U6A ZD3A
component class U_VNF1248+3F8_B3: C24F C25F C26F C27F C28F C29F C30F C31F C32F C33F C125F D6F D8F R43F R44F R45F R47F R48F R49F R50F R51F R53F R54F R55F R56F R57F R58F R59F T4F T5F T6F U4F ZD1F
component class U_VNF1248+3F8_B2: C24E C25E C26E C27E C28E C29E C30E C31E C32E C33E C125E D6E D8E R43E R44E R45E R47E R48E R49E R50E R51E R53E R54E R55E R56E R57E R58E R59E T4E T5E T6E U4E ZD1E
component class U_VNF1248+3F8_B1: C24D C25D C26D C27D C28D C29D C30D C31D C32D C33D C125D D6D D8D R43D R44D R45D R47D R48D R49D R50D R51D R53D R54D R55D R56D R57D R58D R59D T4D T5D T6D U4D ZD1D
component class U_VNF1248+3F8_A3: C24C C25C C26C C27C C28C C29C C30C C31C C32C C33C C125C D6C D8C R43C R44C R45C R47C R48C R49C R50C R51C R53C R54C R55C R56C R57C R58C R59C T4C T5C T6C U4C ZD1C
component class U_VNF1248+3F8_A2: C24B C25B C26B C27B C28B C29B C30B C31B C32B C33B C125B D6B D8B R43B R44B R45B R47B R48B R49B R50B R51B R53B R54B R55B R56B R57B R58B R59B T4B T5B T6B U4B ZD1B
component class U_VNF1248+3F8_A1: C24A C25A C26A C27A C28A C29A C30A C31A C32A C33A C125A D6A D8A R43A R44A R45A R47A R48A R49A R50A R51A R53A R54A R55A R56A R57A R58A R59A T4A T5A T6A U4A ZD1A
component class U_VNF9Q20SF_A1: C15 C16 C17 C18 C19 C20 C21 C22 C23 D4 D5 R29 R30 R31 R32 R33 R34 R35 R36 R37 R38 R39 R40 R41 R42 T3 U3
component class U_VNF9D5SF_B2: C8B C9B C10B C11B C12B C13B C14B D2B D3B R15B R16B R17B R18B R19B R20B R21B R22B R23B R24B R25B R26B R27B R28B T2B U2B
component class U_VNF9D5SF_B1: C8A C9A C10A C11A C12A C13A C14A D2A D3A R15A R16A R17A R18A R19A R20A R21A R22A R23A R24A R25A R26A R27A R28A T2A U2A
component class U_VNF9D1M5Q_B2: C1D C2D C3D C4D C5D C6D C7D D1D JP1D JP2D R1D R2D R3D R4D R5D R6D R7D R8D R9D R10D R11D R12D R13D R14D T1D U1D
component class U_VNF9D1M5Q_B1: C1C C2C C3C C4C C5C C6C C7C D1C JP1C JP2C R1C R2C R3C R4C R5C R6C R7C R8C R9C R10C R11C R12C R13C R14C T1C U1C
component class U_VNF9D1M5Q_A2: C1B C2B C3B C4B C5B C6B C7B D1B JP1B JP2B R1B R2B R3B R4B R5B R6B R7B R8B R9B R10B R11B R12B R13B R14B T1B U1B
component class U_VNF9D1M5Q_A1: C1A C2A C3A C4A C5A C6A C7A D1A JP1A JP2A R1A R2A R3A R4A R5A R6A R7A R8A R9A R10A R11A R12A R13A R14A T1A U1A
component class U_PMIC: C62 C63 C64 C65 C66 C67 C68 C69 C70 C71 C72 C73 C74 C75 C76 C77 C78 C79 C80 C81 C82 C83 C84 C85 C86 C87 C88 C89 C90 C91 C92 C93 C94 C95 C96 C97 C98 C99 C100 C101 C102 C103 C104 C105 C106 C107 C108 C122 C123 C124 CR1 D25 D26 J2 JP3 L1 L2 L3 Q1 Q2 R46 R52 R65 R71 R85 R91 R152 R153 R154 R155 R156 R157 R158 R159 R160 R161 R162 R163 R164 R165 R166 R167 R168 R170 R171 R172 R173 R199 R200 R201 R203 T20 U9 U10 U12
component class U_MCU: C60 C61 D12 D13 D20 D21 D22 D23 D24 J1 JP6 LED1 LED2 LED8 LED9 LED10 R119 R120 R121 R122 R123 R124 R125 R126 R127 R128 R129 R130 R131 R132 R133 R134 R135 R136 R137 R138 R139 R140 R141 R142 R143 R144 R145 R146 R147 R148 R149 R150 R151 R169 R179 R195 R196 R202 R204 R205 TP1 TP2 TP3 TP4 TP9 TP12 TP13 TP14 TP15 TP16 TP17 TP18 TP19 TP20 TP21 TP24 TP25 TP26 TP27 TP28 TP29 TP30 TP31 TP32 TP33 TP34 TP35 TP36 TP37 TP38 TP39 TP40 TP41 TP42 TP43 TP44 TP45 TP46 TP47 TP48 TP49 TP51 TP52 TP53 U8 X1
component class U_L99SP08_B1: C54B C55B C56B C57B C58B C59B D14B R101B R102B R103B R104B R105B R106B R107B R108B R109B R110B R197B R198B U7B
component class U_L99SP08_A1: C54A C55A C56A C57A C58A C59A D14A R101A R102A R103A R104A R105A R106A R107A R108A R109A R110A R197A R198A U7A
component class U_GroupB: D16 D27 P7 P8 P9 P10 P11 P12 R115 R116 R117 R118 Tr_d10 Tr_d13
component class U_GroupA: D15 P1 P2 P3 P4 P5 P6 R111 R112 R113 R114 Tr_d3 Tr_d4
component class U_Connectors: D17 D18 D19 LED3 LED4 LED5 LED6 LED7 P13 P14 P15 P16 R190 R191 R192 R193 R194 TP5 TP6 TP7 TP8 TP10 TP11 TP22 TP23 TP50 Tr_d18 Tr_d19 Tr_d20 Tr_d21
differential pair TRX: +TRX_P -TRX_N
differential pair ISNS8B: +ISNS8B_P -ISNS8B_N
differential pair ISNS8A: +ISNS8A_P -ISNS8A_N
differential pair ISNS5B: +ISNS5B_P -ISNS5B_N
differential pair ISNS5A: +ISNS5A_P -ISNS5A_N
differential pair ISNS3F: +ISNS3F_P -ISNS3F_N
differential pair ISNS3E: +ISNS3E_P -ISNS3E_N
differential pair ISNS3D: +ISNS3D_P -ISNS3D_N
differential pair ISNS3C: +ISNS3C_P -ISNS3C_N
differential pair ISNS3B: +ISNS3B_P -ISNS3B_N
differential pair ISNS3A: +ISNS3A_P -ISNS3A_N

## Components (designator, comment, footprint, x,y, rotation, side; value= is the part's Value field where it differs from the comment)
C1A "100nF" C0603_ROUND 102,86.25 r90 top (schematic designator C1)
C1B "100nF" C0603_ROUND 117,86.25 r90 top (schematic designator C1)
C1C "100nF" C0603_ROUND 138.5,188.75 r270 top (schematic designator C1)
C1D "100nF" C0603_ROUND 123.5,188.75 r270 top (schematic designator C1)
C2A "1nF" C0603_ROUND 103,89.25 r90 top (schematic designator C2)
C2B "1nF" C0603_ROUND 118,89.25 r90 top (schematic designator C2)
C2C "1nF" C0603_ROUND 137.5,185.75 r270 top (schematic designator C2)
C2D "1nF" C0603_ROUND 122.5,185.75 r270 top (schematic designator C2)
C3A "220nF" C0603_ROUND 94,100 r270 top (schematic designator C3)
C3B "220nF" C0603_ROUND 109,98.5 r90 top (schematic designator C3)
C3C "220nF" C0603_ROUND 146.5,176.5 r270 top (schematic designator C3)
C3D "220nF" C0603_ROUND 131.5,176.5 r270 top (schematic designator C3)
C4A "220nF" C0603_ROUND 92,100.75 r0 top (schematic designator C4)
C4B "220nF" C0603_ROUND 107,98.5 r0 top (schematic designator C4)
C4C "220nF" C0603_ROUND 148.5,176.5 r180 top (schematic designator C4)
C4D "220nF" C0603_ROUND 133.5,176.5 r180 top (schematic designator C4)
C5A "100nF" C0603_ROUND 106.25,93 r270 top (schematic designator C5)
C5B "100nF" C0603_ROUND 121.25,93 r270 top (schematic designator C5)
C5C "100nF" C0603_ROUND 134.25,182 r90 top (schematic designator C5)
C5D "100nF" C0603_ROUND 119.25,182 r90 top (schematic designator C5)
C6A "10nF" C0603_ROUND 105.25,102.5 r135 top (schematic designator C6)
C6B "10nF" C0603_ROUND 120.25,102.5 r135 top (schematic designator C6)
C6C "10nF" C0603_ROUND 135.25,172.5 r315 top (schematic designator C6)
C6D "10nF" C0603_ROUND 120.25,172.5 r315 top (schematic designator C6)
C7A "10nF" C0603_ROUND 92.75,103.5 r45 top (schematic designator C7)
C7B "10nF" C0603_ROUND 108.75,102.5 r45 top (schematic designator C7)
C7C "10nF" C0603_ROUND 146.75,172.5 r225 top (schematic designator C7)
C7D "10nF" C0603_ROUND 131.75,172.5 r225 top (schematic designator C7)
C8A "100nF" C0603_ROUND 144,130.5 r90 top (schematic designator C8)
C8B "100nF" C0603_ROUND 129,130.5 r90 top (schematic designator C8)
C9A "1nF" C0603_ROUND 142.25,133.5 r90 top (schematic designator C9)
C9B "1nF" C0603_ROUND 127.25,133.5 r90 top (schematic designator C9)
C10A "220nF" C0603_ROUND 136,139.475 r90 top (schematic designator C10)
C10B "220nF" C0603_ROUND 120.75,139.75 r90 top (schematic designator C10)
C11A "220nF" C0603_ROUND 136.75,137 r180 top (schematic designator C11)
C11B "220nF" C0603_ROUND 120.75,137.75 r0 top (schematic designator C11)
C12A "2.2uF" C0603_ROUND 148.25,138 r90 top (schematic designator C12)
C12B "2.2uF" C0603_ROUND 133.25,138 r90 top (schematic designator C12)
C13A "10nF" C0603_ROUND 147.5,144.5 r180 top (schematic designator C13)
C13B "10nF" C0603_ROUND 132.5,144.5 r180 top (schematic designator C13)
C14A "10nF" C0603_ROUND 134,143.25 r0 top (schematic designator C14)
C14B "10nF" C0603_ROUND 125,146 r180 top (schematic designator C14)
C15 "100nF" C0603_ROUND 104.25,147 r270 top
C16 "1nF" C0603_ROUND 102.75,143.25 r270 top
C17 "220nF" C0603_ROUND 112.75,139.25 r90 top
C18 "220nF" C0603_ROUND 112.75,137.25 r180 top
C19 "2.2uF" C0603_ROUND 97.775,138.25 r0 top
C20 "10nF" C0603_ROUND 108.75,128.25 r0 top
C21 "10nF" C0603_ROUND 105.25,128.25 r180 top
C22 "10nF" C0603_ROUND 98.548,133.452 r315 top
C23 "10nF" C0603_ROUND 112.5,128.25 r180 top
C24A "470nF" C0603_ROUND 81.75,122.5 r90 top (schematic designator C24)
C24B "470nF" C0603_ROUND 80.5,75.75 r90 top (schematic designator C24)
C24C "470nF" C0603_ROUND 84.75,57.75 r90 top (schematic designator C24)
C24D "470nF" C0603_ROUND 165.25,124.25 r270 top (schematic designator C24)
C24E "470nF" C0603_ROUND 165.25,98.25 r270 top (schematic designator C24)
C24F "470nF" C0603_ROUND 165.25,72.25 r270 top (schematic designator C24)
C25A "220nF" C0603_ROUND 79.75,132.75 r0 top (schematic designator C25)
C25B "220nF" C0603_ROUND 78.5,86 r0 top (schematic designator C25)
C25C "220nF" C0603_ROUND 82.75,68 r0 top (schematic designator C25)
C25D "220nF" C0603_ROUND 167.25,114 r180 top (schematic designator C25)
C25E "220nF" C0603_ROUND 167.25,88 r180 top (schematic designator C25)
C25F "220nF" C0603_ROUND 167.25,62 r180 top (schematic designator C25)
C26A "1uF" C0603_ROUND 78.25,119 r180 top (schematic designator C26)
C26B "1uF" C0603_ROUND 74.25,76.5 r0 top (schematic designator C26)
C26C "1uF" C0603_ROUND 78.5,58.5 r0 top (schematic designator C26)
C26D "1uF" C0603_ROUND 171.5,123.5 r180 top (schematic designator C26)
C26E "1uF" C0603_ROUND 171.5,97.5 r180 top (schematic designator C26)
C26F "1uF" C0603_ROUND 171.5,71.5 r180 top (schematic designator C26)
C27A "470nF" C0603_ROUND 80.25,122.5 r270 top (schematic designator C27)
C27B "470nF" C0603_ROUND 79,75.75 r270 top (schematic designator C27)
C27C "470nF" C0603_ROUND 83.25,57.75 r270 top (schematic designator C27)
C27D "470nF" C0603_ROUND 166.75,124.25 r90 top (schematic designator C27)
C27E "470nF" C0603_ROUND 166.75,98.25 r90 top (schematic designator C27)
C27F "470nF" C0603_ROUND 166.75,72.25 r90 top (schematic designator C27)
C28A "1uF" C0603_ROUND 78.75,122.5 r270 top (schematic designator C28)
C28B "1uF" C0603_ROUND 77.5,75.75 r270 top (schematic designator C28)
C28C "1uF" C0603_ROUND 81.75,57.75 r270 top (schematic designator C28)
C28D "1uF" C0603_ROUND 168.25,124.25 r90 top (schematic designator C28)
C28E "1uF" C0603_ROUND 168.25,98.25 r90 top (schematic designator C28)
C28F "1uF" C0603_ROUND 168.25,72.25 r90 top (schematic designator C28)
C29A "470nF" C0603_ROUND 77.5,122.5 r270 top (schematic designator C29)
C29B "470nF" C0603_ROUND 76.25,75.75 r270 top (schematic designator C29)
C29C "470nF" C0603_ROUND 80.5,57.75 r270 top (schematic designator C29)
C29D "470nF" C0603_ROUND 169.5,124.25 r90 top (schematic designator C29)
C29E "470nF" C0603_ROUND 169.5,98.25 r90 top (schematic designator C29)
C29F "470nF" C0603_ROUND 169.5,72.25 r90 top (schematic designator C29)
C30A "470nF" C0603_ROUND 78.25,120.25 r0 top (schematic designator C30)
C30B "470nF" C0603_ROUND 74.25,75 r180 top (schematic designator C30)
C30C "470nF" C0603_ROUND 78.5,57 r180 top (schematic designator C30)
C30D "470nF" C0603_ROUND 171.5,125 r0 top (schematic designator C30)
C30E "470nF" C0603_ROUND 171.5,99 r0 top (schematic designator C30)
C30F "470nF" C0603_ROUND 171.5,73 r0 top (schematic designator C30)
C31A "100nF" C0603_ROUND 83.25,122.5 r90 top (schematic designator C31)
C31B "100nF" C0603_ROUND 82,75.75 r90 top (schematic designator C31)
C31C "100nF" C0603_ROUND 86.25,57.75 r90 top (schematic designator C31)
C31D "100nF" C0603_ROUND 163.75,124.25 r270 top (schematic designator C31)
C31E "100nF" C0603_ROUND 163.75,98.25 r270 top (schematic designator C31)
C31F "100nF" C0603_ROUND 163.75,72.25 r270 top (schematic designator C31)
C32A "10nF" C0603_ROUND 52.75,128.5 r180 top (schematic designator C32)
C32B "10nF" C0603_ROUND 52.75,102.5 r180 top (schematic designator C32)
C32C "10nF" C0603_ROUND 52.75,76.5 r180 top (schematic designator C32)
C32D "10nF" C0603_ROUND 197.25,105 r0 top (schematic designator C32)
C32E "10nF" C0603_ROUND 197.25,79 r0 top (schematic designator C32)
C32F "10nF" C0603_ROUND 197.25,53 r0 top (schematic designator C32)
C33A "1uF" C0603_ROUND 79.75,134 r0 top (schematic designator C33)
C33B "1uF" C0603_ROUND 78.5,87.25 r0 top (schematic designator C33)
C33C "1uF" C0603_ROUND 82.75,69.25 r0 top (schematic designator C33)
C33D "1uF" C0603_ROUND 167.25,112.75 r180 top (schematic designator C33)
C33E "1uF" C0603_ROUND 167.25,86.75 r180 top (schematic designator C33)
C33F "1uF" C0603_ROUND 167.25,60.75 r180 top (schematic designator C33)
C34A "470nF" C0603_ROUND 95.25,189 r90 top (schematic designator C34)
C34B "470nF" C0603_ROUND 153.75,198.25 r270 top (schematic designator C34)
C35A "220nF" C0603_ROUND 93.75,200.5 r0 top (schematic designator C35)
C35B "220nF" C0603_ROUND 155.25,186.75 r180 top (schematic designator C35)
C36A "1uF" C0603_ROUND 89,189.75 r0 top (schematic designator C36)
C36B "1uF" C0603_ROUND 160,197.5 r180 top (schematic designator C36)
C37A "470nF" C0603_ROUND 93.75,189 r270 top (schematic designator C37)
C37B "470nF" C0603_ROUND 155.25,198.25 r90 top (schematic designator C37)
C38A "1uF" C0603_ROUND 92.25,189 r270 top (schematic designator C38)
C38B "1uF" C0603_ROUND 156.75,198.25 r90 top (schematic designator C38)
C39A "470nF" C0603_ROUND 91,189 r270 top (schematic designator C39)
C39B "470nF" C0603_ROUND 158,198.25 r90 top (schematic designator C39)
C40A "470nF" C0603_ROUND 89,188.25 r180 top (schematic designator C40)
C40B "470nF" C0603_ROUND 160,199 r0 top (schematic designator C40)
C41A "100nF" C0603_ROUND 96.5,189 r90 top (schematic designator C41)
C41B "100nF" C0603_ROUND 152.5,198.25 r270 top (schematic designator C41)
C42A "10nF" C0603_ROUND 47,168.25 r90 top (schematic designator C42)
C42B "10nF" C0603_ROUND 202.25,168.25 r90 top (schematic designator C42)
C43A "1uF" C0603_ROUND 93.75,199.25 r0 top (schematic designator C43)
C43B "1uF" C0603_ROUND 155.25,188 r180 top (schematic designator C43)
C44A "470nF" C0603_ROUND 94.25,153 r90 top (schematic designator C44)
C44B "470nF" C0603_ROUND 155.5,145.25 r270 top (schematic designator C44)
C45A "220nF" C0603_ROUND 92.75,163.25 r0 top (schematic designator C45)
C45B "220nF" C0603_ROUND 159,134.25 r180 top (schematic designator C45)
C46A "1uF" C0603_ROUND 88,153.75 r0 top (schematic designator C46)
C46B "1uF" C0603_ROUND 161.75,144.5 r180 top (schematic designator C46)
C47A "470nF" C0603_ROUND 92.75,153 r270 top (schematic designator C47)
C47B "470nF" C0603_ROUND 157,145.25 r90 top (schematic designator C47)
C48A "1uF" C0603_ROUND 91.25,153 r270 top (schematic designator C48)
C48B "1uF" C0603_ROUND 158.5,145.25 r90 top (schematic designator C48)
C49A "470nF" C0603_ROUND 90,153 r270 top (schematic designator C49)
C49B "470nF" C0603_ROUND 159.75,145.25 r90 top (schematic designator C49)
C50A "470nF" C0603_ROUND 88,152.25 r180 top (schematic designator C50)
C50B "470nF" C0603_ROUND 161.75,146 r0 top (schematic designator C50)
C51A "100nF" C0603_ROUND 95.5,153 r90 top (schematic designator C51)
C51B "100nF" C0603_ROUND 154.25,145.25 r270 top (schematic designator C51)
C52A "10nF" C0603_ROUND 47,163.75 r270 top (schematic designator C52)
C52B "10nF" C0603_ROUND 202.25,163.75 r270 top (schematic designator C52)
C53A "1uF" C0603_ROUND 92.75,164.5 r0 top (schematic designator C53)
C53B "1uF" C0603_ROUND 159,133 r180 top (schematic designator C53)
C54A "220nF" C0603_ROUND 75,98.25 r0 top (schematic designator C54)
C54B "220nF" C0603_ROUND 167.5,169.25 r180 top (schematic designator C54)
C55A "22uF" "C_EL 6.3x6.1mm VP" 89,96.25 r180 top (schematic designator C55)
C55B "22uF" "C_EL 6.3x6.1mm VP" 158.5,173 r0 top (schematic designator C55)
C56A "220nF" C0603_ROUND 73,97.75 r90 top (schematic designator C56)
C56B "220nF" C0603_ROUND 169.5,170.25 r270 top (schematic designator C56)
C57A "470nF" C0603_ROUND 72.25,107.25 r180 top (schematic designator C57)
C57B "470nF" C0603_ROUND 170.25,161 r0 top (schematic designator C57)
C58A "100nF" C0603_ROUND 75,108.5 r180 top (schematic designator C58)
C58B "100nF" C0603_ROUND 167.5,159.5 r0 top (schematic designator C58)
C59A "1uF" C0603_ROUND 87.5,104.25 r0 top (schematic designator C59)
C59B "1uF" C0603_ROUND 166.5,156.75 r270 top (schematic designator C59)
C60 "10pF" C0603_ROUND 142.25,65.5 r0 bottom
C61 "10pF" C0603_ROUND 140.25,63.25 r180 bottom
C62 "4,7uF" R0805_ROUND 119.789,43.551 r225 bottom
C63 "100nF" C0603_ROUND 118.5,44.5 r225 bottom
C64 "100nF" C0603_ROUND 133,46 r315 bottom
C65 "100nF" C0603_ROUND 137.25,52 r45 bottom
C66 "100nF" C0603_ROUND 123.75,63.5 r135 bottom
C67 "100nF" C0603_ROUND 112.75,52.5 r135 bottom
C68 "100nF" C0603_ROUND 127.5,40.5 r315 bottom
C69 "100nF" C0603_ROUND 126.25,39.25 r315 bottom
C70 "100nF" C0603_ROUND 120.75,42.25 r225 bottom
C71 "100nF" C0603_ROUND 133.25,56 r45 bottom
C72 "100nF" C0603_ROUND 117.5,57.25 r135 bottom
C73 "10nF" C0603_ROUND 116.5,56.25 r135 bottom
C74 "100nF" C0603_ROUND 115,54.75 r135 bottom
C75 "2.2uF" C0603_ROUND 118.5,58.25 r135 bottom
C76 "47nF" C0603_ROUND 116.5,46.5 r225 bottom
C77 "10nF" C0603_ROUND 117.5,45.5 r225 bottom
C78 "47nF" C0603_ROUND 132,45 r315 bottom
C79 "10nF" C0603_ROUND 131,44 r315 bottom
C80 "47nF" C0603_ROUND 136.25,53 r45 bottom
C81 "10nF" C0603_ROUND 134.25,55 r45 bottom
C82 "47nF" C0603_ROUND 126.75,63 r45 bottom
C83 "10nF" C0603_ROUND 127.75,62 r45 bottom
C84 "2.2uF" C0603_ROUND 115.5,47.5 r225 bottom
C85 "2.2uF" C0603_ROUND 135.25,54 r45 bottom
C86 "10uF" C1206_ROUND 158.25,49.75 r180 top
C87 "220nF" C0603_ROUND 158.25,51.5 r180 top
C88 "1uF" C0603_ROUND 207,49 r180 top
C89 "1uF" C0603_ROUND 207,47.75 r180 top
C90 "1uF" C0603_ROUND 209,48.5 r90 top
C91 "1uF" C0603_ROUND 210.25,48.5 r90 top
C92 "2.2uF" C0603_ROUND 207,46.5 r180 top
C93 "10uF" C1206_ROUND 165.25,43.5 r270 top
C94 "10uF" C1206_ROUND 162.75,43.5 r270 top
C95 "100uF" "C_EL 10x10.5mm VP" 179.75,43 r180 top
C96 "10uF" C1206_ROUND 170.25,43.5 r270 top
C97 "10uF" C1206_ROUND 167.75,43.5 r270 top
C98 "100uF" "C_EL 10x10.5mm VP" 179.75,31.75 r180 top
C99 "220nF" C0603_ROUND 164,37 r90 top
C100 "2.2uF" C0603_ROUND 195.25,44.25 r0 top
C101 "10uF" C1206_ROUND 163.75,49 r180 top
C102 "10uF" C1206_ROUND 163.75,46.838 r180 top
C103 "10uF" C1206_ROUND 169,46.838 r0 top
C104 "10uF" C1206_ROUND 169,49 r0 top
C105 "2,2uF" C0805_ROUND 212.75,40 r270 top
C106 "1uF" C0603_ROUND 217,36.75 r90 top
C107 "2,2uF" C0805_ROUND 215.75,40.5 r180 top
C108 "1uF" C0603_ROUND 197.25,40.75 r90 top
C109 "100nF" C0603_ROUND 89.25,34 r270 bottom
C110 "100nF" C0603_ROUND 84.25,33 r180 bottom
C111 "100nF" C0603_ROUND 52,42.25 r180 top
C112 "100nF" C0603_ROUND 52,43.75 r180 top
C113 "470nF" C0603_ROUND 84.25,34.25 r180 bottom
C114 "100nF" C0603_ROUND 84.25,35.5 r180 bottom
C115 "220nF" C0603_ROUND 84.25,36.75 r180 bottom
C116 "220nF" C0603_ROUND 84.25,39.25 r180 bottom
C117 "4.7nF" C0603_ROUND 54.25,43.75 r270 bottom
C118 "470nF" C0603_ROUND 87.25,40.75 r90 bottom
C119 "100nF" C0603_ROUND 83.25,42 r0 top
C120 "10pF" C0603_ROUND 89.25,46 r270 bottom
C121 "10pF" C0603_ROUND 85.25,44.5 r90 bottom
C122 "1uF" C0603_ROUND 198.5,40.75 r90 top
C123 "1uF" C0603_ROUND 198,37.25 r0 top
C124 "1uF" C0603_ROUND 198,38.5 r0 top
C125A "22uF" "C_EL 6.3x6.1mm VP" 86.75,138.25 r180 top (schematic designator C125)
C125B "22uF" "C_EL 6.3x6.1mm VP" 89,88.75 r180 top (schematic designator C125)
C125C "22uF" "C_EL 6.3x6.1mm VP" 89.75,72.25 r180 top (schematic designator C125)
C125D "22uF" "C_EL 6.3x6.1mm VP" 161.5,110 r0 top (schematic designator C125)
C125E "22uF" "C_EL 6.3x6.1mm VP" 161.5,84 r0 top (schematic designator C125)
C125F "22uF" "C_EL 6.3x6.1mm VP" 161.5,58 r0 top (schematic designator C125)
C126A "22uF" "C_EL 6.3x6.1mm VP" 93.5,183 r0 top (schematic designator C126)
C126B "22uF" "C_EL 6.3x6.1mm VP" 165.25,180.75 r180 top (schematic designator C126)
C127A "22uF" "C_EL 6.3x6.1mm VP" 101.5,167 r180 top (schematic designator C127)
C127B "22uF" "C_EL 6.3x6.1mm VP" 171.75,131.5 r180 top (schematic designator C127)
CR1 "ESDCAN03-2BWY" SOT323-3L_STM 204.75,42 r0 top
CR2 "PESD2ETH1G-T" SOT23 49.384,43.94 r270 bottom
D1A "BAT54-Y" SOT323-3L_STM 105.5,86.25 r90 top value=40V (schematic designator D1)
D1B "BAT54-Y" SOT323-3L_STM 120.5,86.25 r90 top value=40V (schematic designator D1)
D1C "BAT54-Y" SOT323-3L_STM 135,188.75 r270 top value=40V (schematic designator D1)
D1D "BAT54-Y" SOT323-3L_STM 120,188.75 r270 top value=40V (schematic designator D1)
D2A "BAT54-Y" SOT323-3L_STM 146.25,131.25 r90 top value=40V (schematic designator D2)
D2B "BAT54-Y" SOT323-3L_STM 131.25,131.25 r90 top value=40V (schematic designator D2)
D3A "BAT54A" SOT323-3L_STM 146.25,135 r90 top value=40V (schematic designator D3)
D3B "BAT54A" SOT323-3L_STM 131.25,135 r90 top value=40V (schematic designator D3)
D4 "BAT54A" SOT323-3L_STM 100.5,143.5 r270 top value=40V
D5 "BAT54-Y" SOT323-3L_STM 97.75,145 r270 top value=40V
D6A "BAT54-Y" SOT323-3L_STM 73.75,122.75 r180 top value=40V (schematic designator D6)
D6B "BAT54-Y" SOT323-3L_STM 69.25,79.5 r90 top value=40V (schematic designator D6)
D6C "BAT54-Y" SOT323-3L_STM 72,58.5 r90 top value=40V (schematic designator D6)
D6D "BAT54-Y" SOT323-3L_STM 178,123.5 r270 top value=40V (schematic designator D6)
D6E "BAT54-Y" SOT323-3L_STM 178,97.5 r270 top value=40V (schematic designator D6)
D6F "BAT54-Y" SOT323-3L_STM 178,71.5 r270 top value=40V (schematic designator D6)
D7A "BAT54-Y" SOT323-3L_STM 88.25,163.5 r270 top value=40V (schematic designator D7)
D7B "BAT54-Y" SOT323-3L_STM 167.5,137 r90 top value=40V (schematic designator D7)
D8A "STPS1L40-Y" SOD123FLAT_STM 81.25,139.75 r270 top value=40V (schematic designator D8)
D8B "STPS1L40-Y" SOD123FLAT_STM 83.25,90.25 r270 top value=40V (schematic designator D8)
D8C "STPS1L40-Y" SOD123FLAT_STM 83,72.25 r0 top value=40V (schematic designator D8)
D8D "STPS1L40-Y" SOD123FLAT_STM 168.787,110 r180 top value=40V (schematic designator D8)
D8E "STPS1L40-Y" SOD123FLAT_STM 168.75,84 r180 top value=40V (schematic designator D8)
D8F "STPS1L40-Y" SOD123FLAT_STM 168.75,58 r180 top value=40V (schematic designator D8)
D9A "STPS1L40-Y" SOD123FLAT_STM 100.25,183 r180 top value=40V (schematic designator D9)
D9B "STPS1L40-Y" SOD123FLAT_STM 158.75,180.75 r0 top value=40V (schematic designator D9)
D10A "STPS1L40-Y" SOD123FLAT_STM 94.75,167 r0 top value=40V (schematic designator D10)
D10B "STPS1L40-Y" SOD123FLAT_STM 165.75,129.5 r90 top value=40V (schematic designator D10)
D11A "BAT54-Y" SOT323-3L_STM 87.5,185 r90 top value=40V (schematic designator D11)
D11B "BAT54-Y" SOT323-3L_STM 159.75,186.5 r90 top value=40V (schematic designator D11)
D12 "BAT54-Y" SOT323-3L_STM 121.75,68.75 r0 bottom value=40V
D13 "BAT54-Y" SOT323-3L_STM 138.5,67.75 r0 bottom value=40V
D14A "STPS360-Y" SOD128FLAT_STM 79,95 r0 top value=60V (schematic designator D14)
D14B "STPS360-Y" SOD128FLAT_STM 166.081,173 r180 top value=60V (schematic designator D14)
D15 "BAT54-Y" SOT323-3L_STM 112.5,142.75 r270 top value=40V
D16 "BAT54-Y" SOT323-3L_STM 136.75,124 r270 top value=40V
D17 "STPS360-Y" SOD128FLAT_STM 69.25,52.5 r270 top value=60V
D18 "STPS360-Y" SOD128FLAT_STM 172.5,52.5 r270 top value=60V
D19 "STPS360-Y" SOD128FLAT_STM 121.25,76 r270 top value=60V
D20 "BAT54-Y" SOT323-3L_STM 115.5,68.25 r135 bottom value=40V
D21 "BAT54-Y" SOT323-3L_STM 129.5,71.5 r45 bottom value=40V
D22 "BAT54-Y" SOT323-3L_STM 110.75,41 r225 bottom value=40V
D23 "BAT54-Y" SOT323-3L_STM 142.75,58.25 r45 bottom value=40V
D24 "BAT54-Y" SOT323-3L_STM 139.5,41.25 r315 bottom value=40V
D25 "BAT54A" SOT323-3L_STM 212,44.5 r0 top value=40V
D26 "BAT54-Y" SOT323-3L_STM 220.25,40.25 r90 top value=40V
D27 "BAT54-Y" SOT323-3L_STM 121,131 r270 top value=40V
D28A "BAT54-Y" SOT323-3L_STM 82,185 r90 top value=40V (schematic designator D28)
D28B "BAT54-Y" SOT323-3L_STM 162.25,195.75 r180 top value=40V (schematic designator D28)
Designator63 "Comment" Sloupek 63.25,103.25 r0 top
Designator63_1 "Comment" Sloupek 180,103.25 r0 top
Designator64 "Comment" Sloupek 63.25,76.75 r0 top
Designator64_1 "Comment" Sloupek 180,77.5 r0 top
Designator65 "Comment" Sloupek 28.75,132.75 r0 top
Designator65_1 "Comment" Sloupek 221.25,132.75 r0 top
Designator66 "Comment" Sloupek 28.75,166 r0 top
Designator66_1 "Comment" Sloupek 221.25,166 r0 top
Designator67 "Comment" Sloupek 28.75,221.25 r0 top
Designator67_1 "Comment" Sloupek 221.25,221.25 r0 top
Designator68 "Comment" Sloupek 77.25,166 r0 top
Designator68_1 "Comment" Sloupek 177.75,165.75 r0 top
Designator69 "Comment" Sloupek 77.25,221.25 r0 top
Designator69_1 "Comment" Sloupek 173,221.25 r0 top
Designator70 "Comment" Sloupek 28.75,49 r0 top
Designator70_1 "Comment" Sloupek 221.25,49 r0 top
Designator71 "Comment" Sloupek 77.25,49 r0 top
Designator71_1 "Comment" Sloupek 176.75,57.25 r0 top
Designator72 "Comment" Pick_place_mark 28.448,41.656 r0 top
Designator73 "Comment" Pick_place_mark 170.688,186.436 r0 top
Designator75 "Comment" Pick_place_mark 83.312,221.234 r180 bottom
Designator76 "Comment" Pick_place_mark 183.642,29.464 r180 bottom
J1 "JTAG_PPC" MLW14 135.25,102.75 r90 top value=JTAG
J2 "Cannon 9M" DSUB_9M 205.385,31.42 r180 top
J3 "Broadreach" "Broadreach connector - TE_2304372-2" 33.95,43 r0 top
JP1A "Always ON selector" R0603_3JUMP 94.75,84.75 r90 top value=JUMP_3_PIN (schematic designator JP1)
JP1B "Always ON selector" R0603_3JUMP 109.75,81.75 r270 top value=JUMP_3_PIN (schematic designator JP1)
JP1C "Always ON selector" R0603_3JUMP 149.25,196.025 r90 top value=JUMP_3_PIN (schematic designator JP1)
JP1D "Always ON selector" R0603_3JUMP 131.75,192.25 r90 top value=JUMP_3_PIN (schematic designator JP1)
JP2A "Always ON selector" R0603_3JUMP 93.5,84.75 r90 top value=JUMP_3_PIN (schematic designator JP2)
JP2B "Always ON selector" R0603_3JUMP 111.25,81.75 r270 top value=JUMP_3_PIN (schematic designator JP2)
JP2C "Always ON selector" R0603_3JUMP 148,196.025 r90 top value=JUMP_3_PIN (schematic designator JP2)
JP2D "Always ON selector" R0603_3JUMP 130.5,192.25 r90 top value=JUMP_3_PIN (schematic designator JP2)
JP3 "JUMP_3_PIN" JUMP_3 180.408,50.202 r180 top
JP4 "JUMP_3_PIN" R0603_3JUMP 83,30.25 r90 top value=47k
JP5 "JUMP_3_PIN" R0603_3JUMP 84.25,31.75 r270 top value=47k
JP6 "JUMP" JUMP_2 126,30.25 r0 top
L1 "10uH" WE-MAPI_5030 158.5,45.75 r180 top
L2 "15uH" IND_LPS6235_COC 168.25,36.75 r0 top
L3 "B82789C0104N001" CAN_CMC 203.5,38 r90 top value=100uH
L4 "DLW43MH201XK2L" DLW43_MUR 56.75,43 r180 top
LED1 "Red LED" D0603_ROUND 139,33.5 r180 top
LED2 "Orange LED" D0603_ROUND 103,53 r0 top
LED3 "Green LED" D0603_ROUND 117.025,198.25 r0 top
LED4 "Green LED" D0603_ROUND 131,198.5 r180 top
LED5 "Green LED" D0603_ROUND 194.286,37.5 r270 top
LED6 "Green LED" D0603_ROUND 192.786,37.5 r270 top
LED7 "Green LED" D0603_ROUND 209.25,40.25 r90 top
LED8 "Orange LED" D0603_ROUND 99.242,33 r0 top
LED9 "Orange LED" D0603_ROUND 101.992,33 r180 top
LED10 "RST" D0603_ROUND 137.75,72.25 r270 top value="Orange LED"
P1 "M8_screw_connector" "MTConn Power Tower M8" 35,194.5 r90 top
P2 "M8_screw_connector" "MTConn Power Tower M8" 35,148.5 r90 top
P3 "M6_screw_connector" "MTConn Power Tower M6" 35,117 r90 top
P4 "M6_screw_connector" "MTConn Power Tower M6" 35,91 r90 top
P5 "M6_screw_connector" "MTConn Power Tower M6" 35,65 r90 top
P6 "GH 8pin" "MTConn GH 8pin" 107,116.5 r0 top value="G&H 8pin"
P7 "M8_screw_connector" "MTConn Power Tower M8" 215.5,194.5 r270 top
P8 "M8_screw_connector" "MTConn Power Tower M8" 215.5,148.5 r270 top
P9 "M6_screw_connector" "MTConn Power Tower M6" 215.5,117 r270 top
P10 "M6_screw_connector" "MTConn Power Tower M6" 215.5,91 r270 top
P11 "M6_screw_connector" "MTConn Power Tower M6" 215.5,65 r270 top
P12 "GH 8pin" "MTConn GH 8pin" 133.513,158.465 r180 top value="G&H 8pin"
P13 "M5_screw_connector" "MTConn Power Tower M5" 115.25,215.75 r0 top
P14 "M8_screw_connector" "MTConn Power Tower M8" 93.25,215 r0 top
P15 "M8_screw_connector" "MTConn Power Tower M8" 157,215 r0 top
P16 "M5_screw_connector" "MTConn Power Tower M5" 135,215.75 r0 top
Q1 "BC68PA" DFN2020-3 120.25,59.75 r315 bottom
Q2 "BSS138" SOT323-3L_STM 215,47.25 r180 top
R1A "330R" R0805_ROUND 101.5,89.5 r270 top (schematic designator R1)
R1B "330R" R0805_ROUND 116.5,89.5 r270 top (schematic designator R1)
R1C "330R" R0805_ROUND 139,185.5 r90 top (schematic designator R1)
R1D "330R" R0805_ROUND 124,185.5 r90 top (schematic designator R1)
R2A "100R" R0603_round 103.25,86.25 r270 top (schematic designator R2)
R2B "100R" R0603_round 118.25,86.25 r270 top (schematic designator R2)
R2C "100R" R0603_round 137.25,188.75 r90 top (schematic designator R2)
R2D "100R" R0603_round 122.25,188.75 r90 top (schematic designator R2)
R3A "330R" R0603_round 104.25,89.25 r90 top (schematic designator R3)
R3B "330R" R0603_round 119.25,89.25 r90 top (schematic designator R3)
R3C "330R" R0603_round 136.25,185.75 r270 top (schematic designator R3)
R3D "330R" R0603_round 121.25,185.75 r270 top (schematic designator R3)
R4A "120R" R0603_round 105,93 r90 top (schematic designator R4)
R4B "120R" R0603_round 120,93 r90 top (schematic designator R4)
R4C "120R" R0603_round 135.5,182 r270 top (schematic designator R4)
R4D "120R" R0603_round 120.5,182 r270 top (schematic designator R4)
R5A "4k7" R0603_round 107.75,86.5 r270 top (schematic designator R5)
R5B "4k7" R0603_round 122.75,86.5 r270 top (schematic designator R5)
R5C "4k7" R0603_round 132.75,188.75 r90 top (schematic designator R5)
R5D "4k7" R0603_round 117.75,188.75 r90 top (schematic designator R5)
R6A "2k7" R0603_round 105.75,95 r0 top (schematic designator R6)
R6B "2k7" R0603_round 120.75,95 r0 top (schematic designator R6)
R6C "2k7" R0603_round 134.75,180 r180 top (schematic designator R6)
R6D "2k7" R0603_round 119.75,180 r180 top (schematic designator R6)
R7A "2k7" R0603_round 105.75,96.25 r0 top (schematic designator R7)
R7B "2k7" R0603_round 120.75,96.25 r0 top (schematic designator R7)
R7C "2k7" R0603_round 134.75,178.75 r180 top (schematic designator R7)
R7D "2k7" R0603_round 119.75,178.75 r180 top (schematic designator R7)
R8A "15k" R0603_round 96,86.25 r270 top (schematic designator R8)
R8B "15k" R0603_round 111,86.25 r270 top (schematic designator R8)
R8C "15k" R0603_round 144.5,188.75 r90 top (schematic designator R8)
R8D "15k" R0603_round 129.5,188.75 r90 top (schematic designator R8)
R9A "15k" R0603_round 96.75,89.25 r270 top (schematic designator R9)
R9B "15k" R0603_round 111.75,89.25 r270 top (schematic designator R9)
R9C "15k" R0603_round 143.75,185.75 r90 top (schematic designator R9)
R9D "15k" R0603_round 128.75,185.75 r90 top (schematic designator R9)
R10A "2k7" R0603_round 97.5,86.25 r270 top (schematic designator R10)
R10B "2k7" R0603_round 112.5,86.25 r270 top (schematic designator R10)
R10C "2k7" R0603_round 143,188.75 r90 top (schematic designator R10)
R10D "2k7" R0603_round 128,188.75 r90 top (schematic designator R10)
R11A "2k7" R0603_round 98.25,89.25 r270 top (schematic designator R11)
R11B "2k7" R0603_round 113.25,89.25 r270 top (schematic designator R11)
R11C "2k7" R0603_round 142.25,185.75 r90 top (schematic designator R11)
R11D "2k7" R0603_round 127.25,185.75 r90 top (schematic designator R11)
R12A "5k6" R0603_round 99,86.25 r270 top (schematic designator R12)
R12B "5k6" R0603_round 114,86.25 r270 top (schematic designator R12)
R12C "5k6" R0603_round 141.5,188.75 r90 top (schematic designator R12)
R12D "5k6" R0603_round 126.5,188.75 r90 top (schematic designator R12)
R13A "5k6" R0603_round 99.75,89.25 r270 top (schematic designator R13)
R13B "5k6" R0603_round 114.75,89.25 r270 top (schematic designator R13)
R13C "5k6" R0603_round 140.75,185.75 r90 top (schematic designator R13)
R13D "5k6" R0603_round 125.75,185.75 r90 top (schematic designator R13)
R14A "180R" R0603_round 100.5,86.25 r270 top (schematic designator R14)
R14B "180R" R0603_round 115.5,86.25 r270 top (schematic designator R14)
R14C "180R" R0603_round 140,188.75 r90 top (schematic designator R14)
R14D "180R" R0603_round 125,188.75 r90 top (schematic designator R14)
R15A "330R" R0805_ROUND 143.75,133.75 r270 top (schematic designator R15)
R15B "330R" R0805_ROUND 128.75,133.75 r270 top (schematic designator R15)
R16A "100R" R0603_round 142.75,130.5 r270 top (schematic designator R16)
R16B "100R" R0603_round 127.75,130.5 r270 top (schematic designator R16)
R17A "330R" R0603_round 148.25,130.5 r90 top (schematic designator R17)
R17B "330R" R0603_round 133.25,130.5 r90 top (schematic designator R17)
R18A "120R" R0603_round 149.5,138 r90 top (schematic designator R18)
R18B "120R" R0603_round 134.5,138 r90 top (schematic designator R18)
R19A "4k7" R0603_round 149.5,130.5 r270 top (schematic designator R19)
R19B "4k7" R0603_round 134.5,130.5 r270 top (schematic designator R19)
R20A "2k7" R0603_round 136.5,133.5 r270 top (schematic designator R20)
R20B "2k7" R0603_round 122,136 r180 top (schematic designator R20)
R21A "2k7" R0603_round 137.75,133.5 r270 top (schematic designator R21)
R21B "2k7" R0603_round 122,134.75 r180 top (schematic designator R21)
R22A "2k7" R0603_round 138.5,130.5 r270 top (schematic designator R22)
R22B "2k7" R0603_round 123.5,130.5 r270 top (schematic designator R22)
R23A "2k7" R0603_round 150.75,130.5 r270 top (schematic designator R23)
R23B "2k7" R0603_round 135.75,130.5 r270 top (schematic designator R23)
R24A "2k7" R0603_round 139.25,133.5 r270 top (schematic designator R24)
R24B "2k7" R0603_round 124.25,133.5 r270 top (schematic designator R24)
R25A "5k6" R0603_round 140,130.5 r270 top (schematic designator R25)
R25B "5k6" R0603_round 125,130.5 r270 top (schematic designator R25)
R26A "5k6" R0603_round 140.75,133.5 r270 top (schematic designator R26)
R26B "5k6" R0603_round 125.75,133.5 r270 top (schematic designator R26)
R27A "180R" R0603_round 141.5,130.5 r270 top (schematic designator R27)
R27B "180R" R0603_round 126.5,130.5 r270 top (schematic designator R27)
R28A "4k7" R0603_round 147,138 r270 top (schematic designator R28)
R28B "4k7" R0603_round 132,138 r270 top (schematic designator R28)
R29 "330R" R0805_ROUND 104.25,143.75 r90 top
R30 "100R" R0603_round 102.75,146.25 r90 top
R31 "330R" R0603_round 95.5,143.25 r270 top
R32 "120R" R0603_round 100.5,138.25 r0 top
R33 "4k7" R0603_round 97.75,137 r0 top
R34 "2k7" R0603_round 110.25,143.25 r90 top
R35 "2k7" R0603_round 109.5,146.25 r90 top
R36 "2k7" R0603_round 108.75,143.25 r90 top
R37 "2k7" R0603_round 100.5,137 r180 top
R38 "2k7" R0603_round 108,146.25 r90 top
R39 "5k6" R0603_round 107.25,143.25 r90 top
R40 "5k6" R0603_round 106.5,146.25 r90 top
R41 "180R" R0603_round 105.75,143.25 r90 top
R42 "4k7" R0603_round 102.75,140.25 r90 top
R43A "0R0002" "R Shunt 3921" 68.5,117 r0 top (schematic designator R43)
R43B "0R0002" "R Shunt 3921" 68.5,91 r0 top (schematic designator R43)
R43C "0R0002" "R Shunt 3921" 68.5,65 r0 top (schematic designator R43)
R43D "0R0002" "R Shunt 3921" 181.5,117 r180 top (schematic designator R43)
R43E "0R0002" "R Shunt 3921" 181.5,91 r180 top (schematic designator R43)
R43F "0R0002" "R Shunt 3921" 181.5,65 r180 top (schematic designator R43)
R44A "1R" R0603_round 51.25,120.5 r180 top (schematic designator R44)
R44B "1R" R0603_round 51.25,94.5 r180 top (schematic designator R44)
R44C "1R" R0603_round 51.25,68.5 r180 top (schematic designator R44)
R44D "1R" R0603_round 198.75,113 r0 top (schematic designator R44)
R44E "1R" R0603_round 198.75,87 r0 top (schematic designator R44)
R44F "1R" R0603_round 198.75,61 r0 top (schematic designator R44)
R45A "47k" R0603_round 51.25,105 r180 top (schematic designator R45)
R45B "47k" R0603_round 51.25,79 r180 top (schematic designator R45)
R45C "47k" R0603_round 51.25,53 r180 top (schematic designator R45)
R45D "47k" R0603_round 198.75,128.5 r0 top (schematic designator R45)
R45E "47k" R0603_round 198.75,102.5 r0 top (schematic designator R45)
R45F "47k" R0603_round 198.75,76.5 r0 top (schematic designator R45)
R46 "15k" R0603_round 153.5,33 r180 top
R47A "1R" R0603_round 51.25,113.5 r0 top (schematic designator R47)
R47B "1R" R0603_round 51.25,87.5 r0 top (schematic designator R47)
R47C "1R" R0603_round 51.25,61.5 r0 top (schematic designator R47)
R47D "1R" R0603_round 198.75,120 r180 top (schematic designator R47)
R47E "1R" R0603_round 198.75,94 r180 top (schematic designator R47)
R47F "1R" R0603_round 198.75,68 r180 top (schematic designator R47)
R48A "2k7" R0603_round 85,126.5 r0 top (schematic designator R48)
R48B "2k7" R0603_round 83.75,79.25 r0 top (schematic designator R48)
R48C "2k7" R0603_round 88,61.75 r0 top (schematic designator R48)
